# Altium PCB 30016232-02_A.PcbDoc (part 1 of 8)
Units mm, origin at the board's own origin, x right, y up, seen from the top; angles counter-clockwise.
Board outline 210 x 130 mm, 8 copper layers (1-TOP, 2-GND, 3-INTOP, 4-PWR, 5-PWR, 6-INBOT, 7-GND, 8-BOTTOM), stack 1.646 mm thick; 754 components, 649 nets, 2976 pads, 2161 vias.
Unrouted connection lines stored in the file: 22.
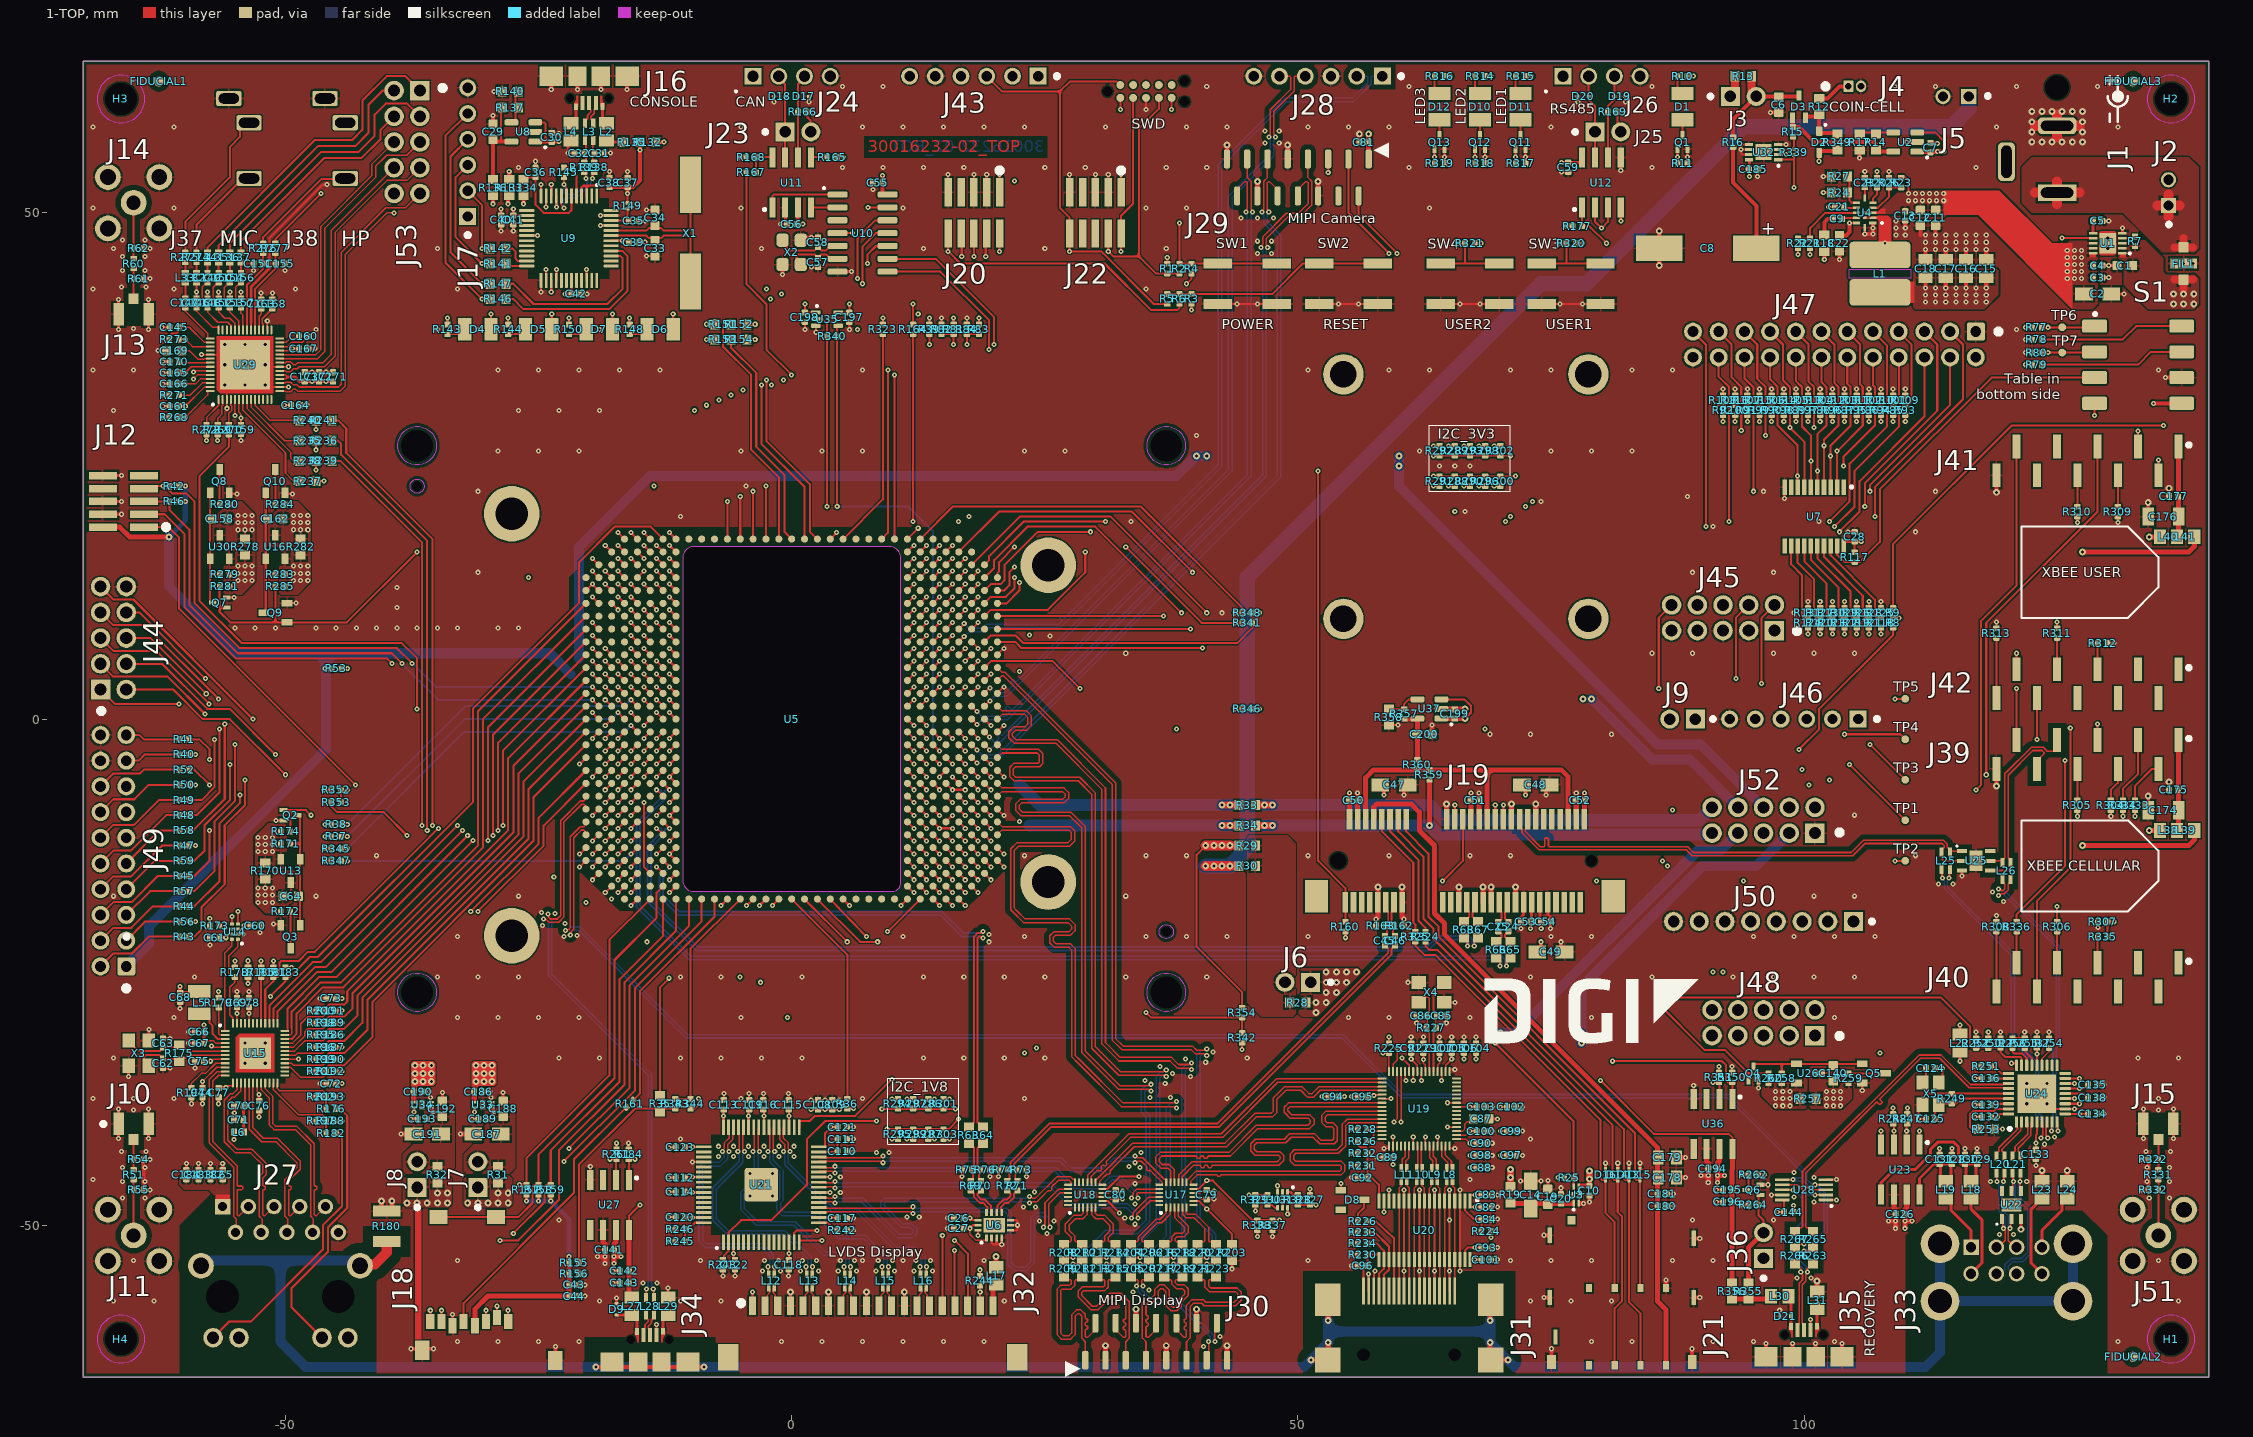
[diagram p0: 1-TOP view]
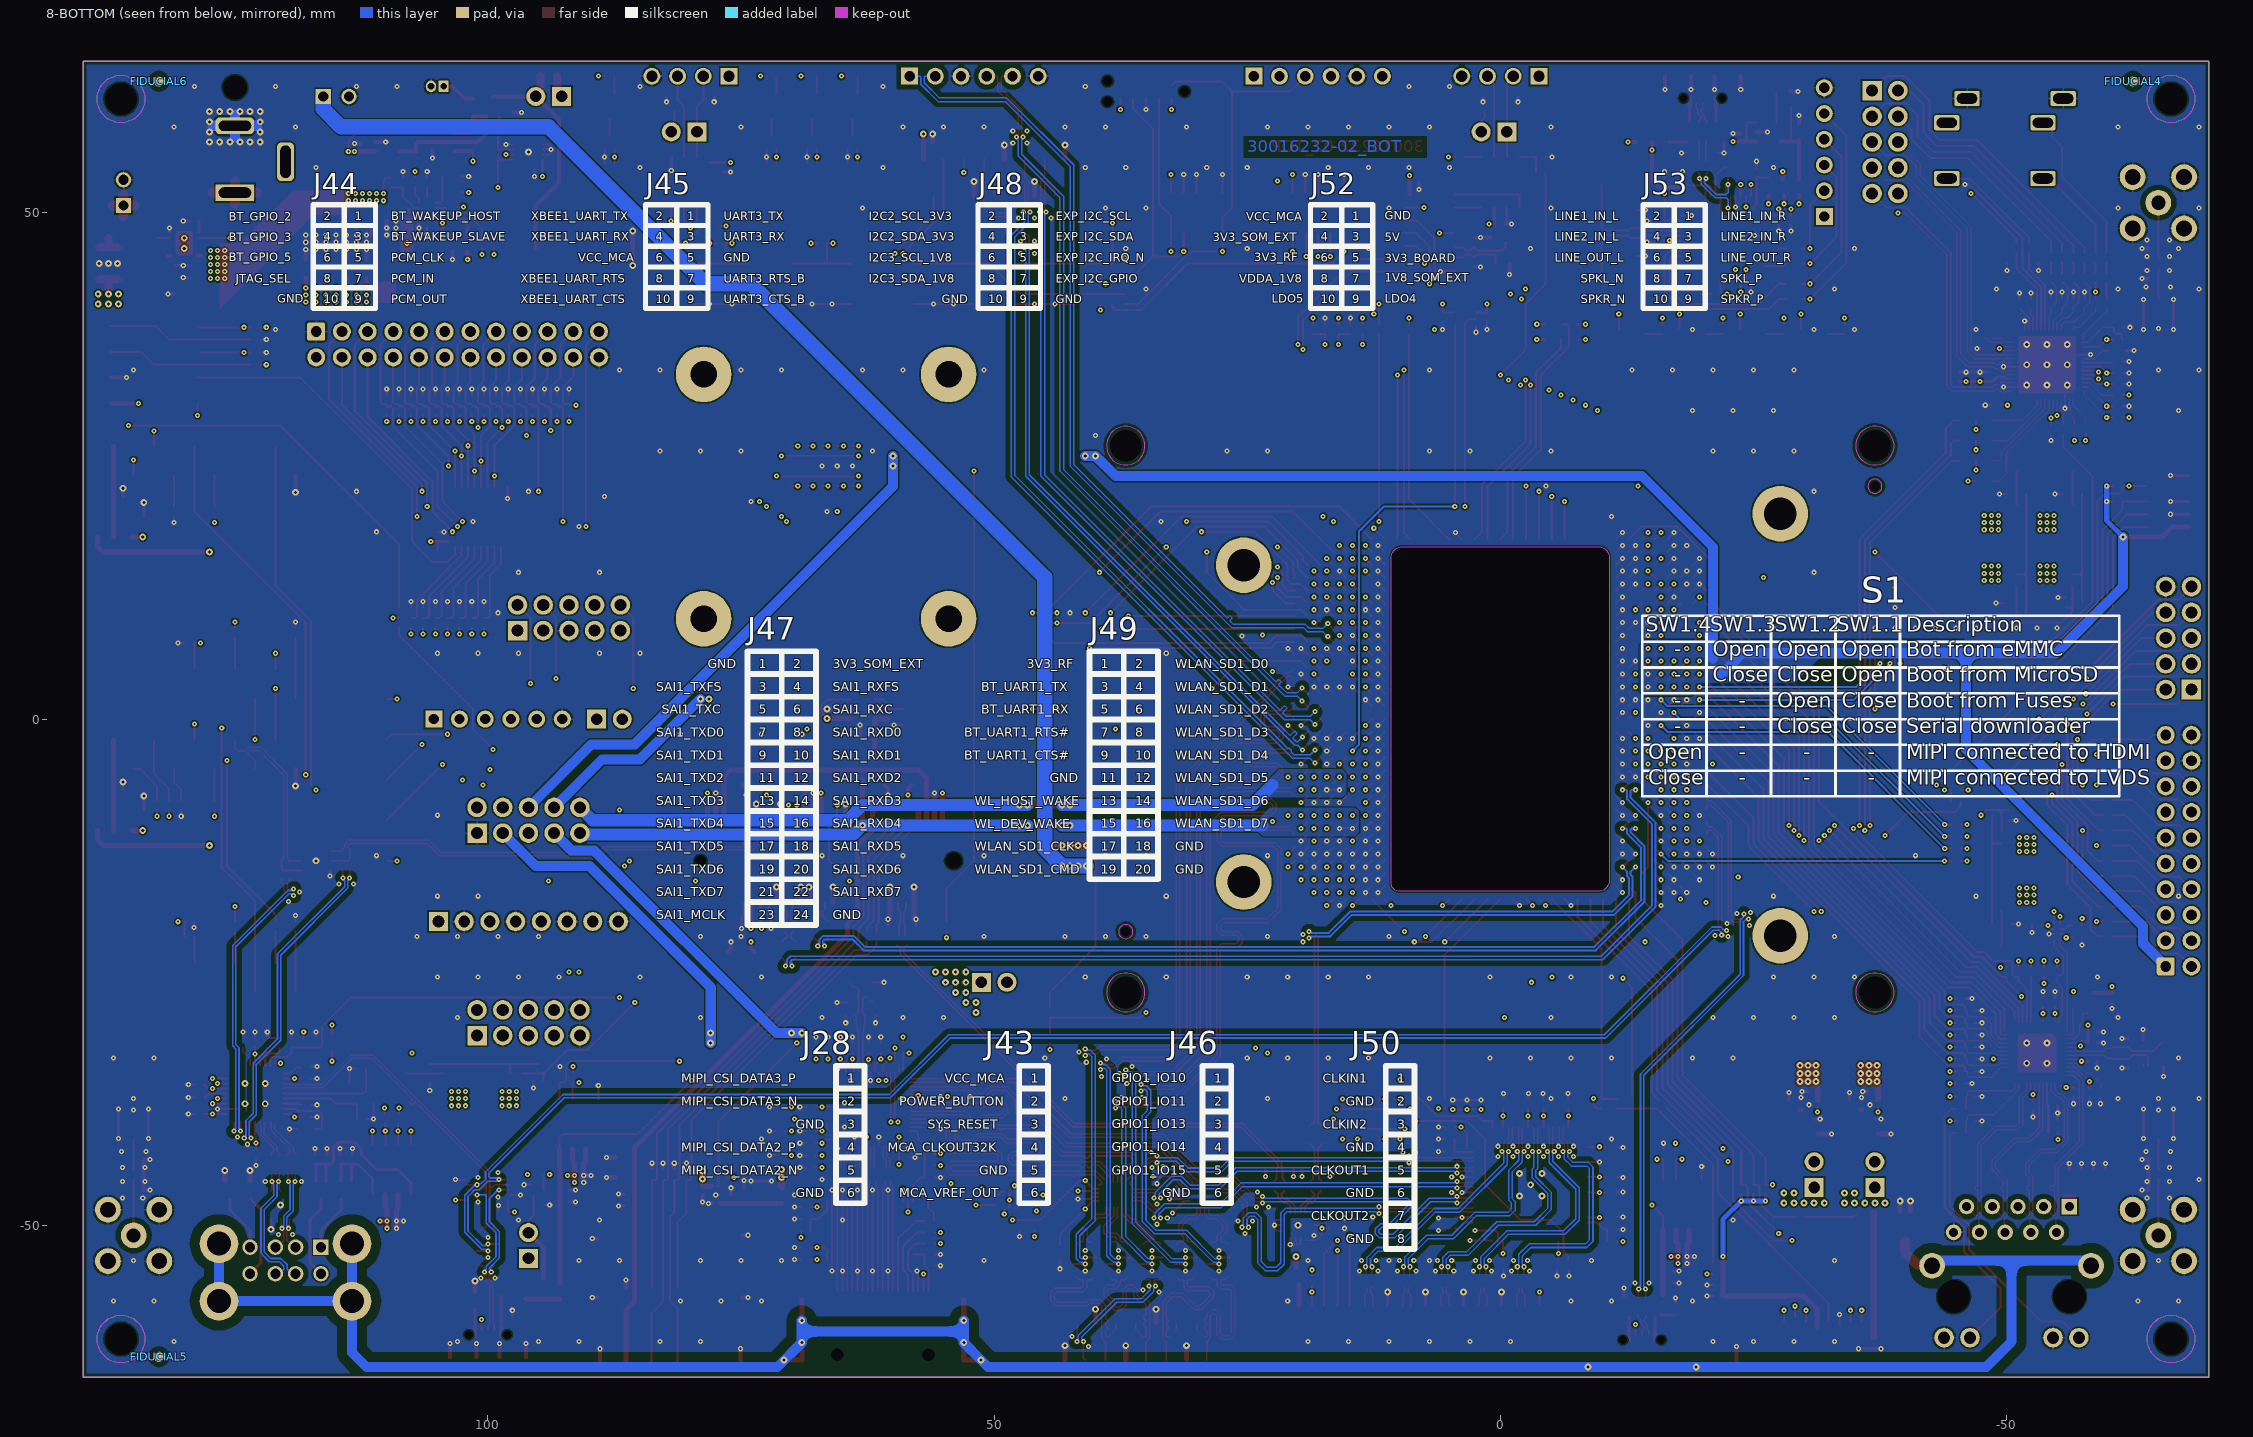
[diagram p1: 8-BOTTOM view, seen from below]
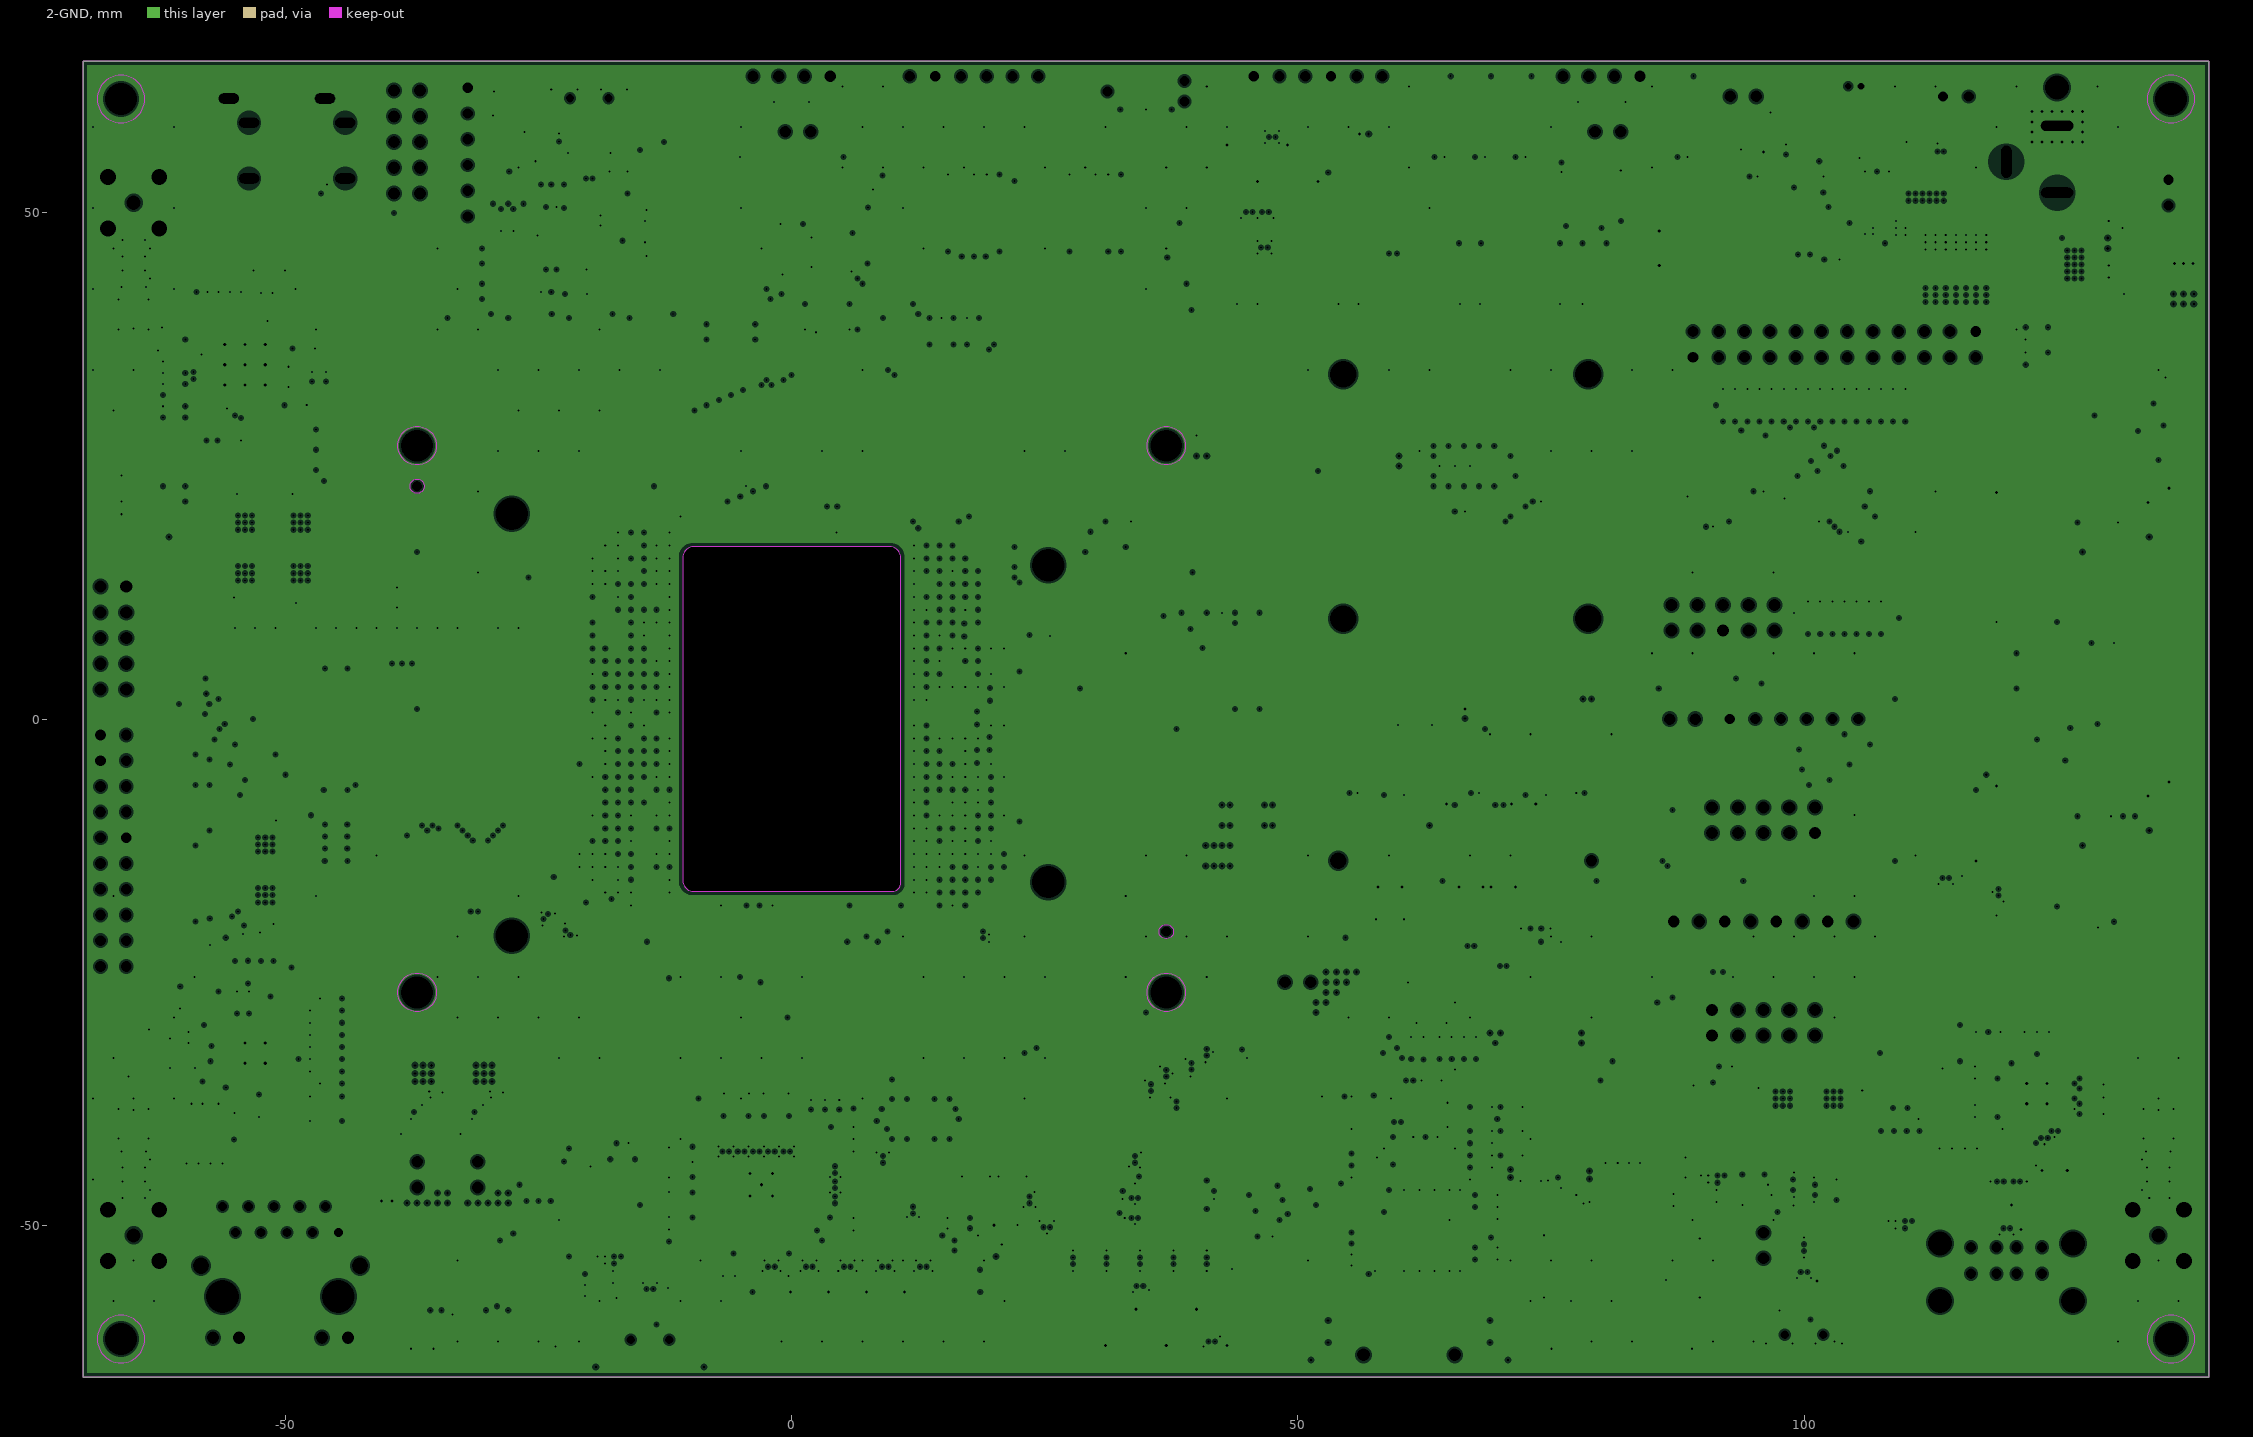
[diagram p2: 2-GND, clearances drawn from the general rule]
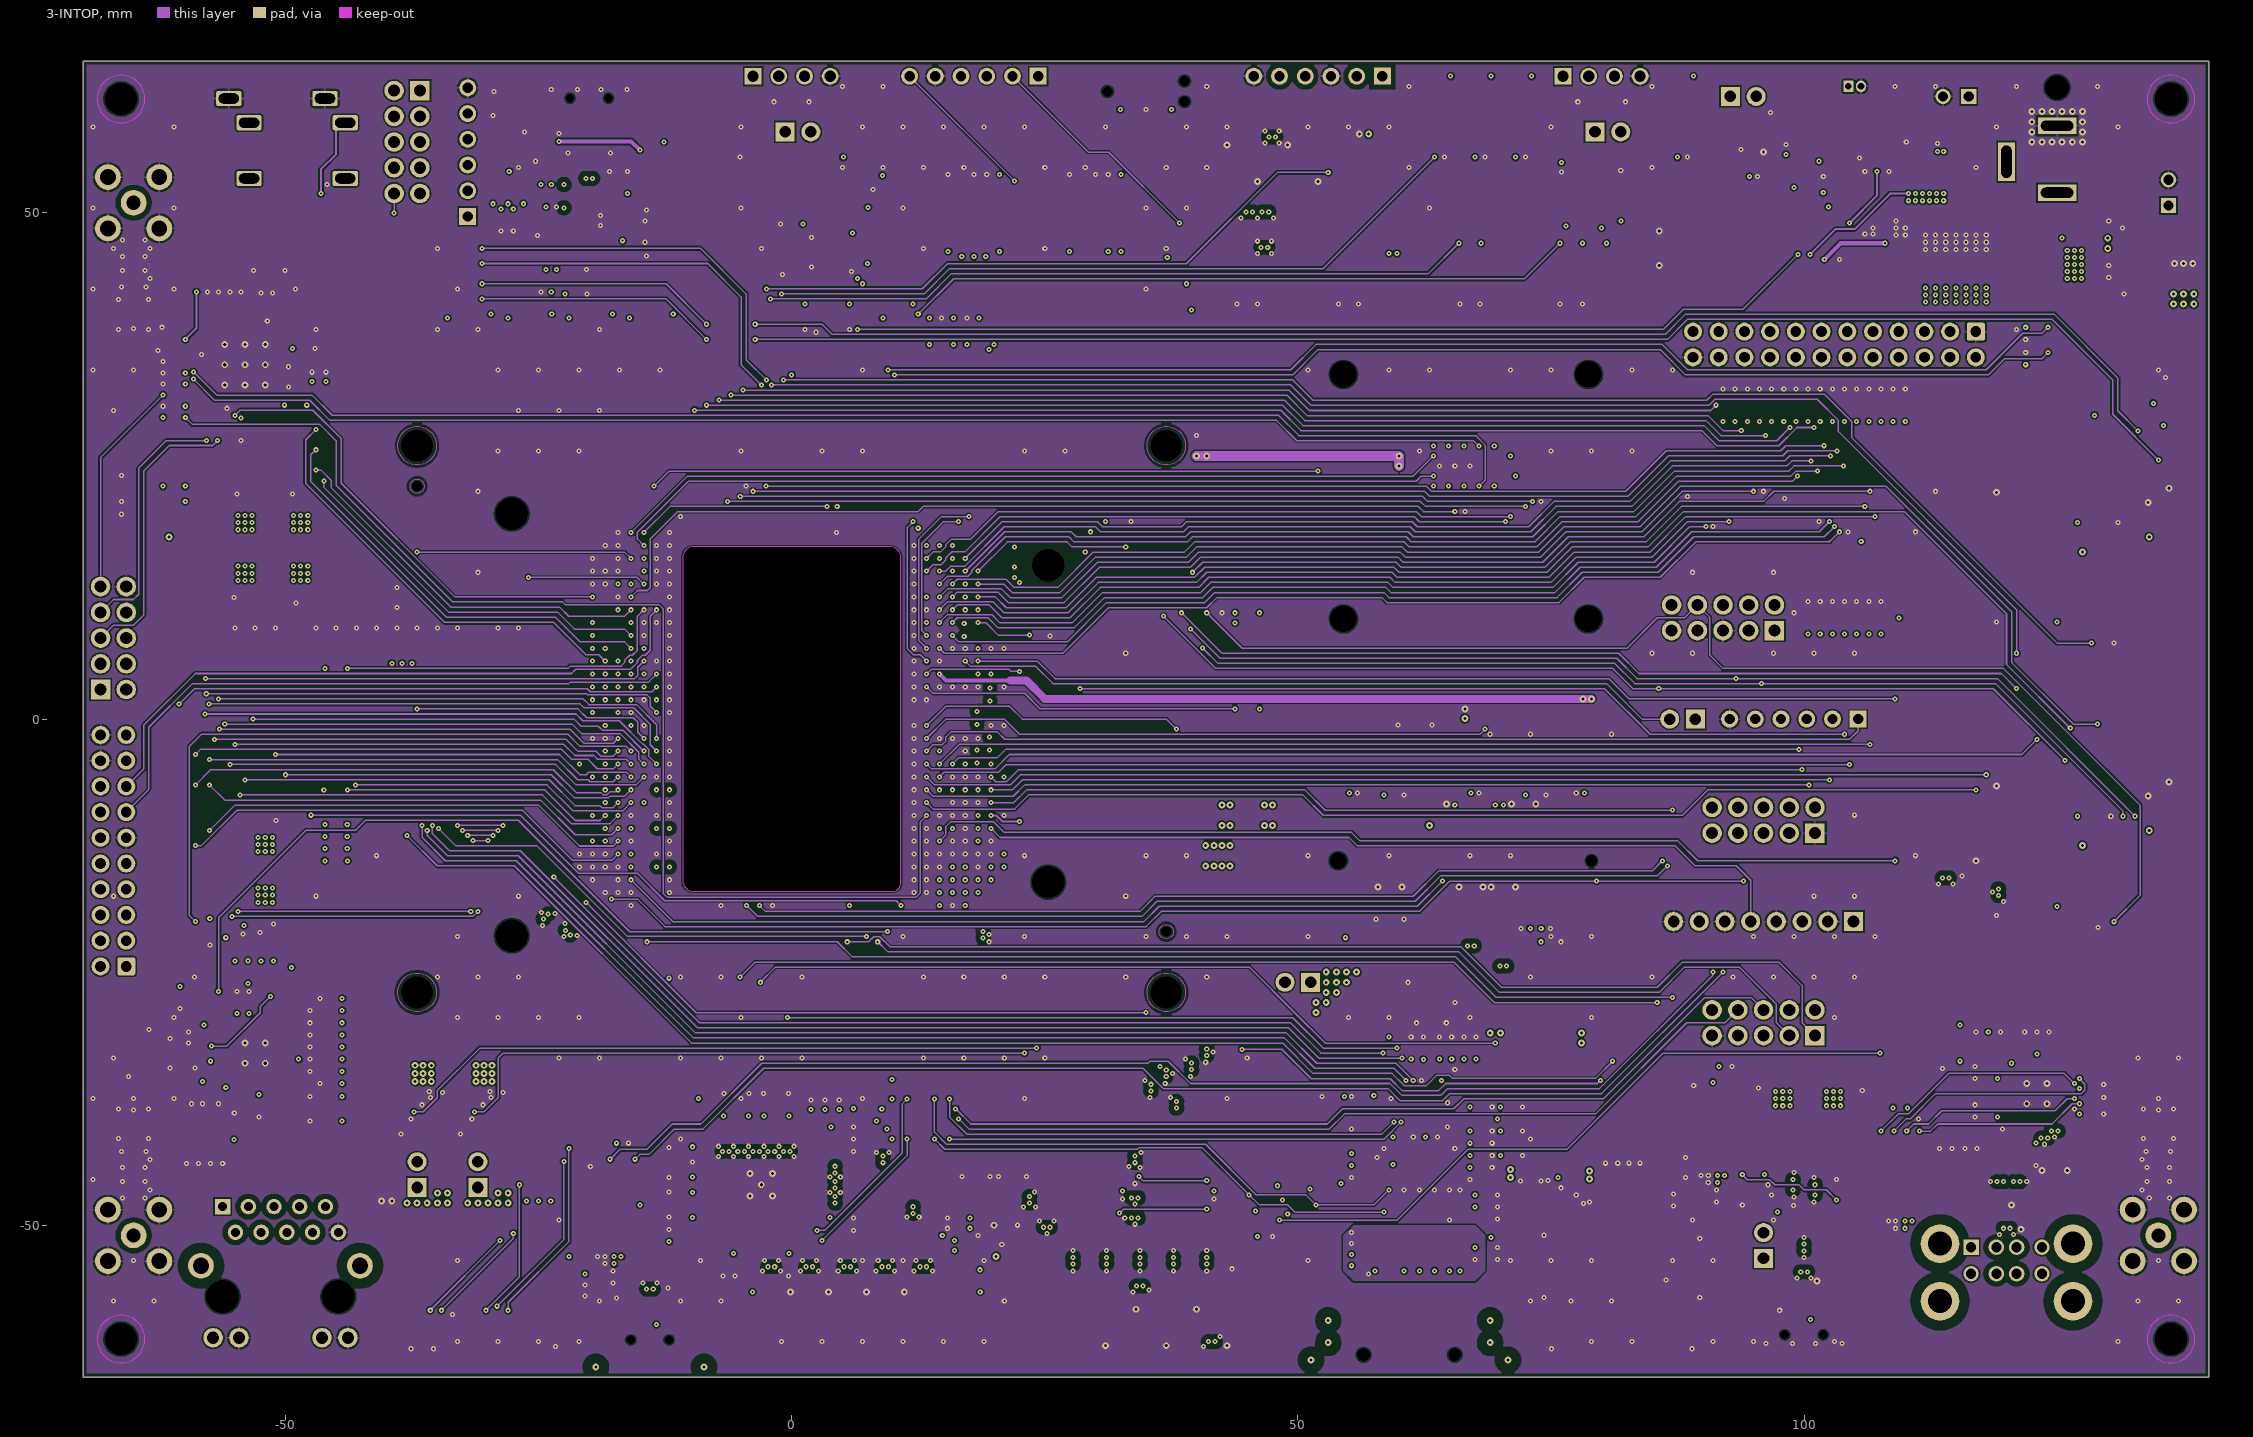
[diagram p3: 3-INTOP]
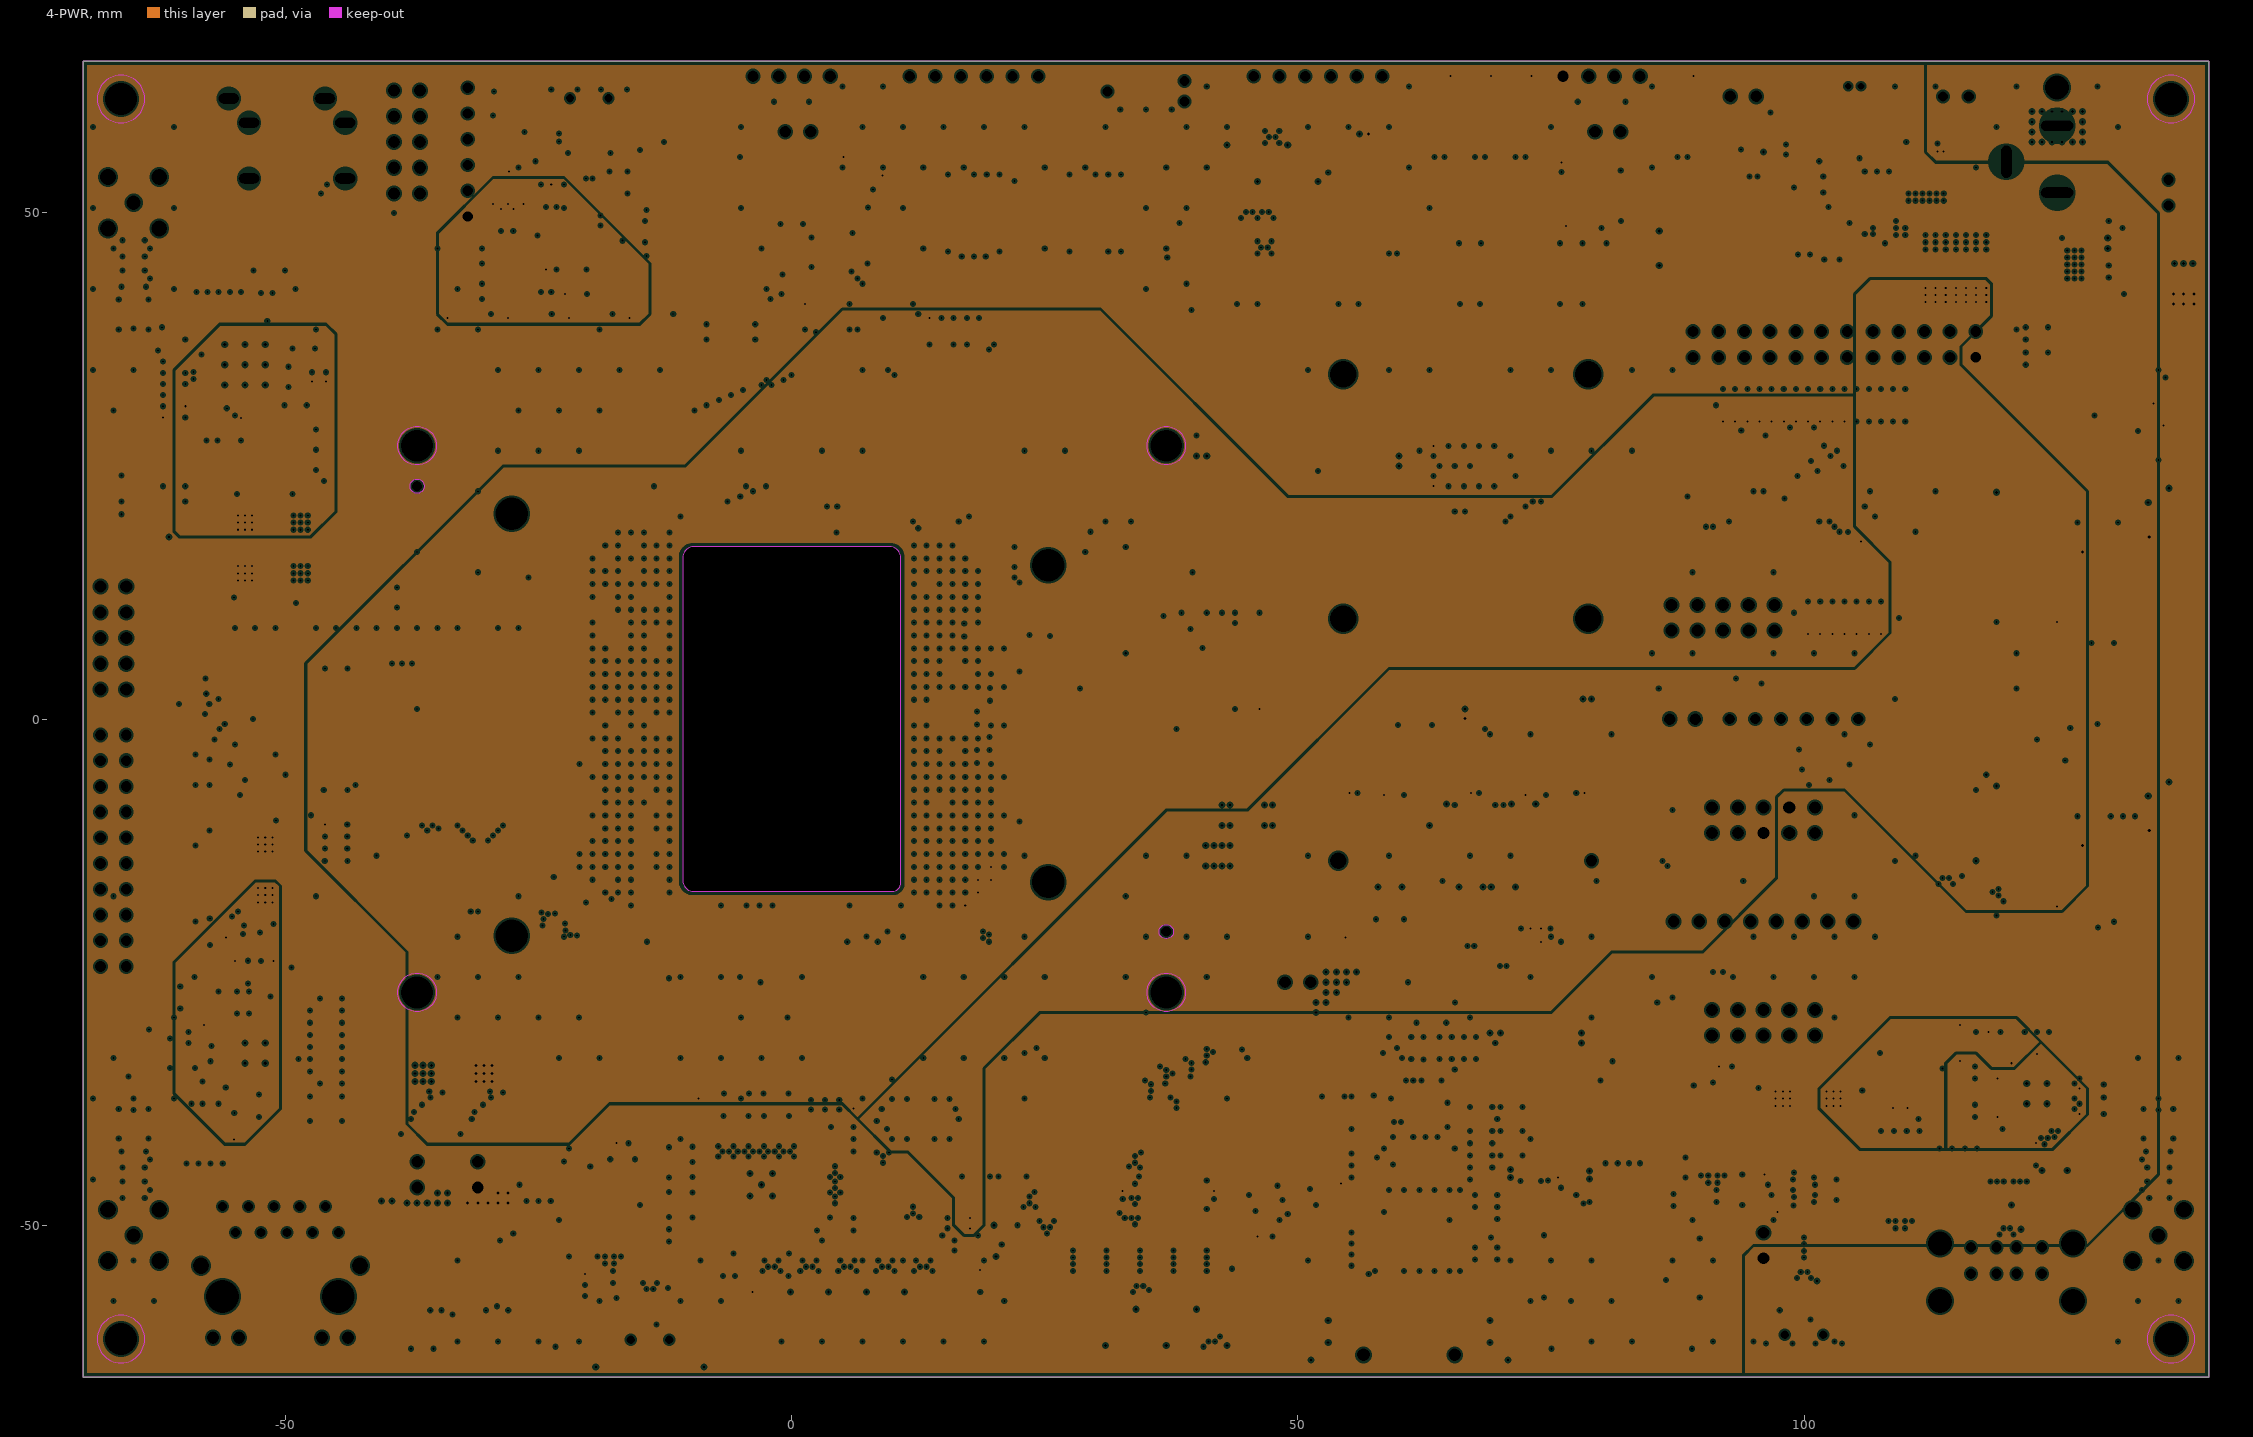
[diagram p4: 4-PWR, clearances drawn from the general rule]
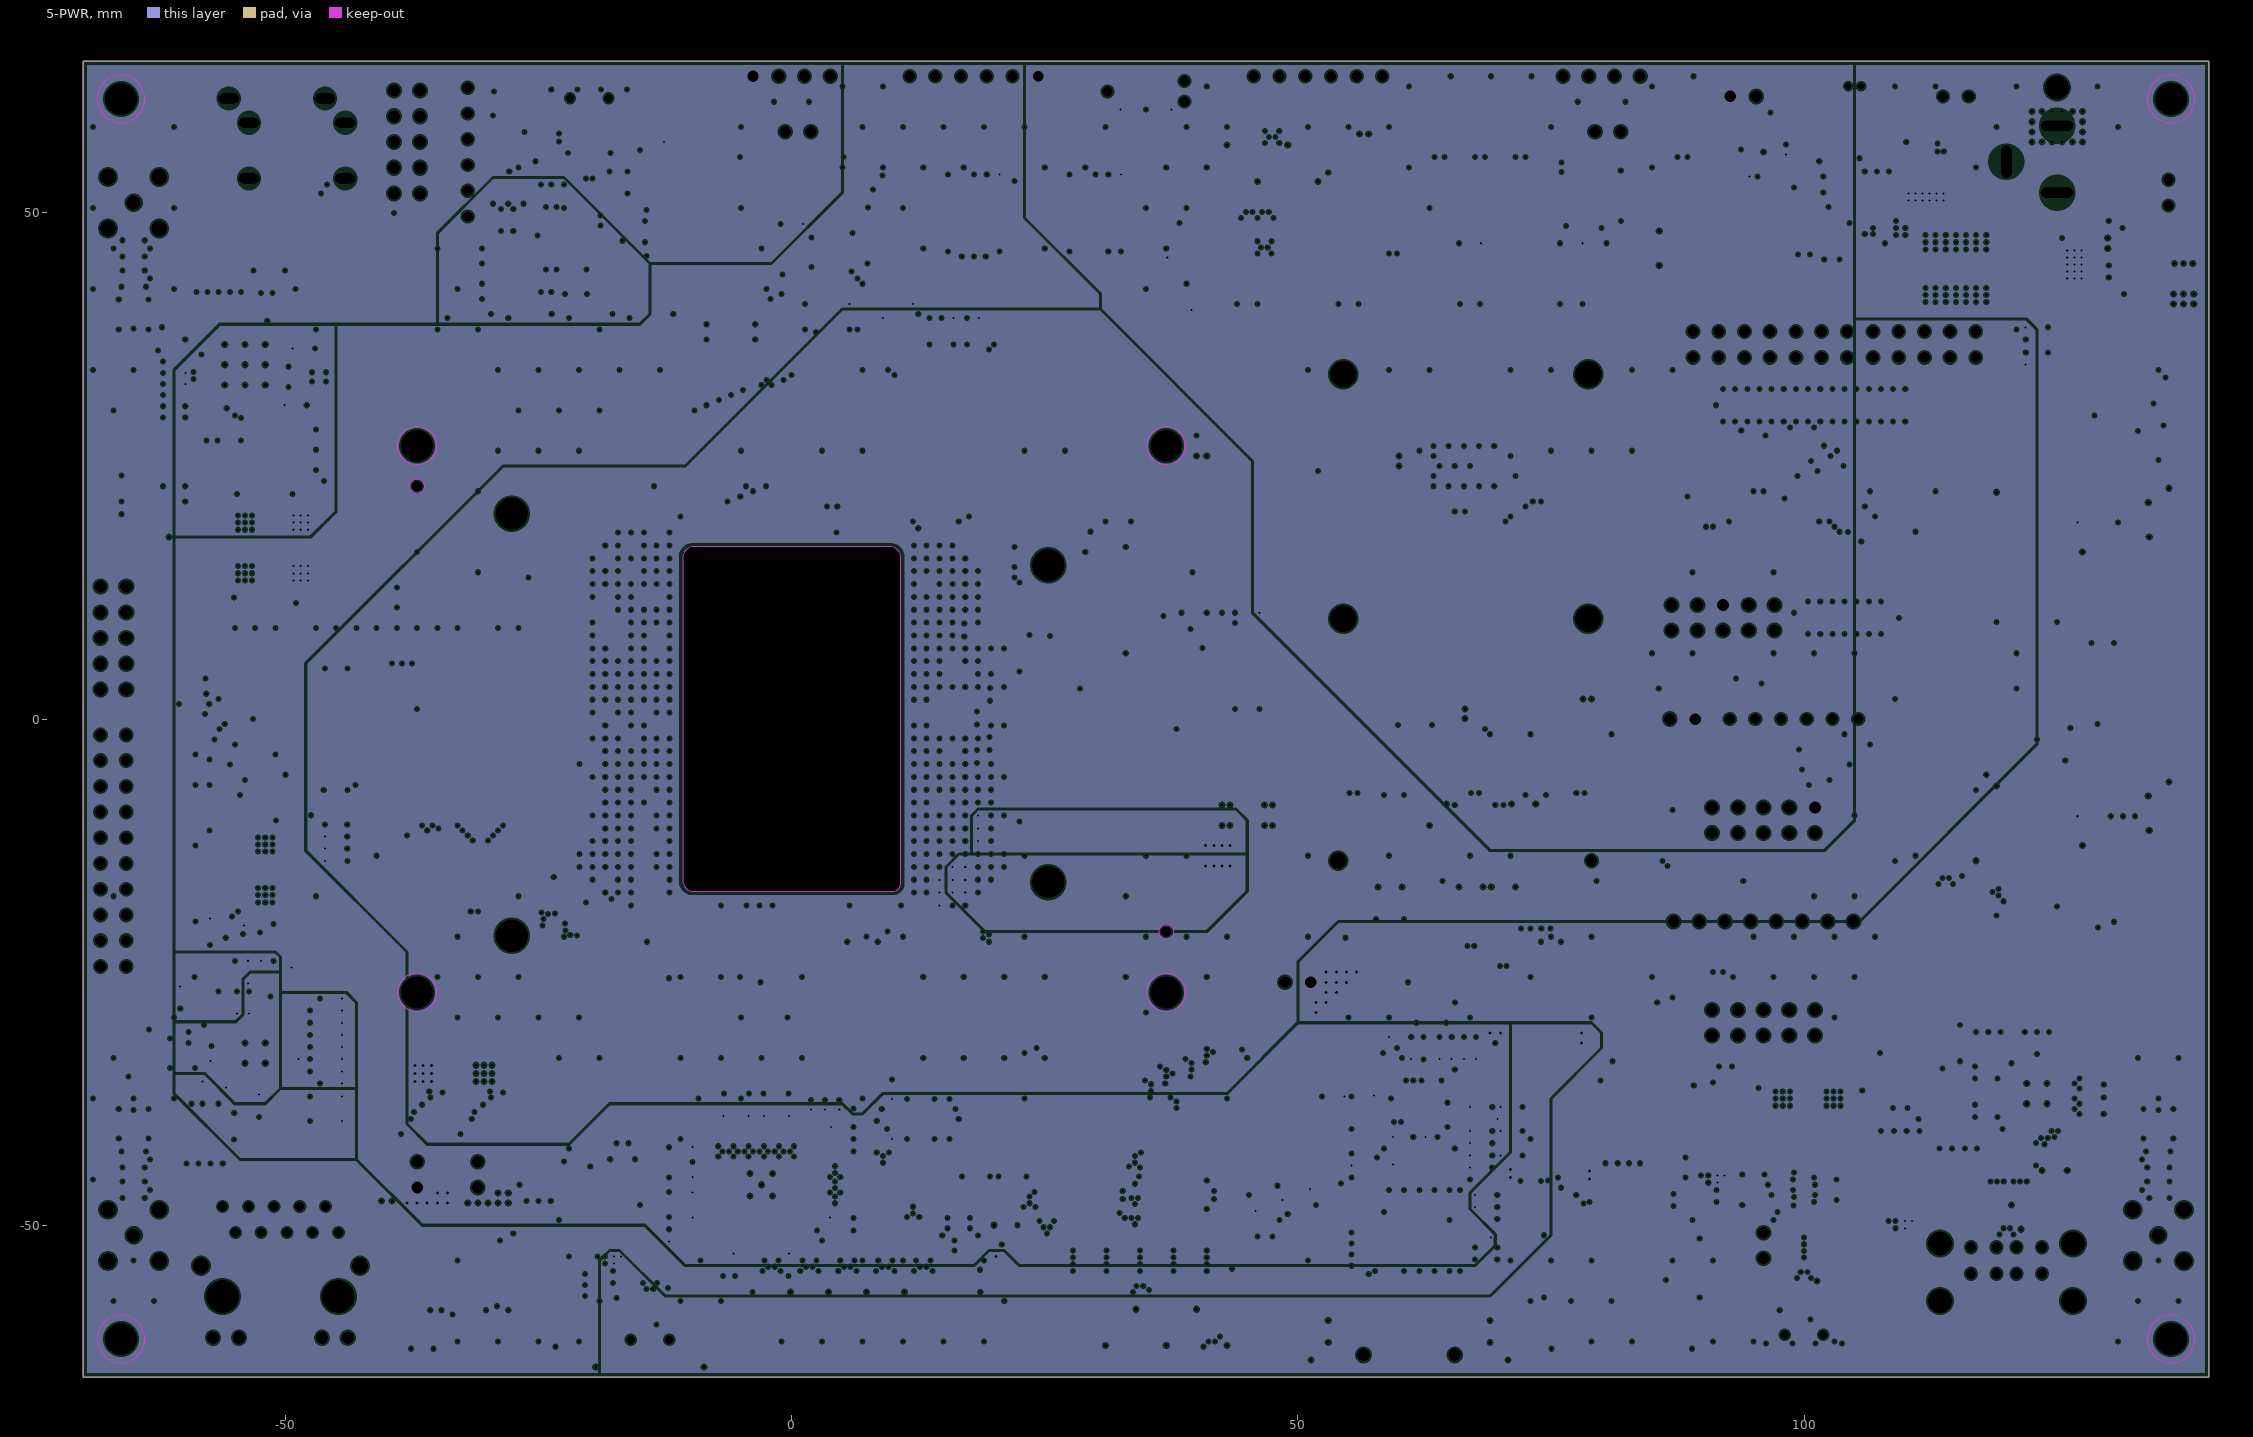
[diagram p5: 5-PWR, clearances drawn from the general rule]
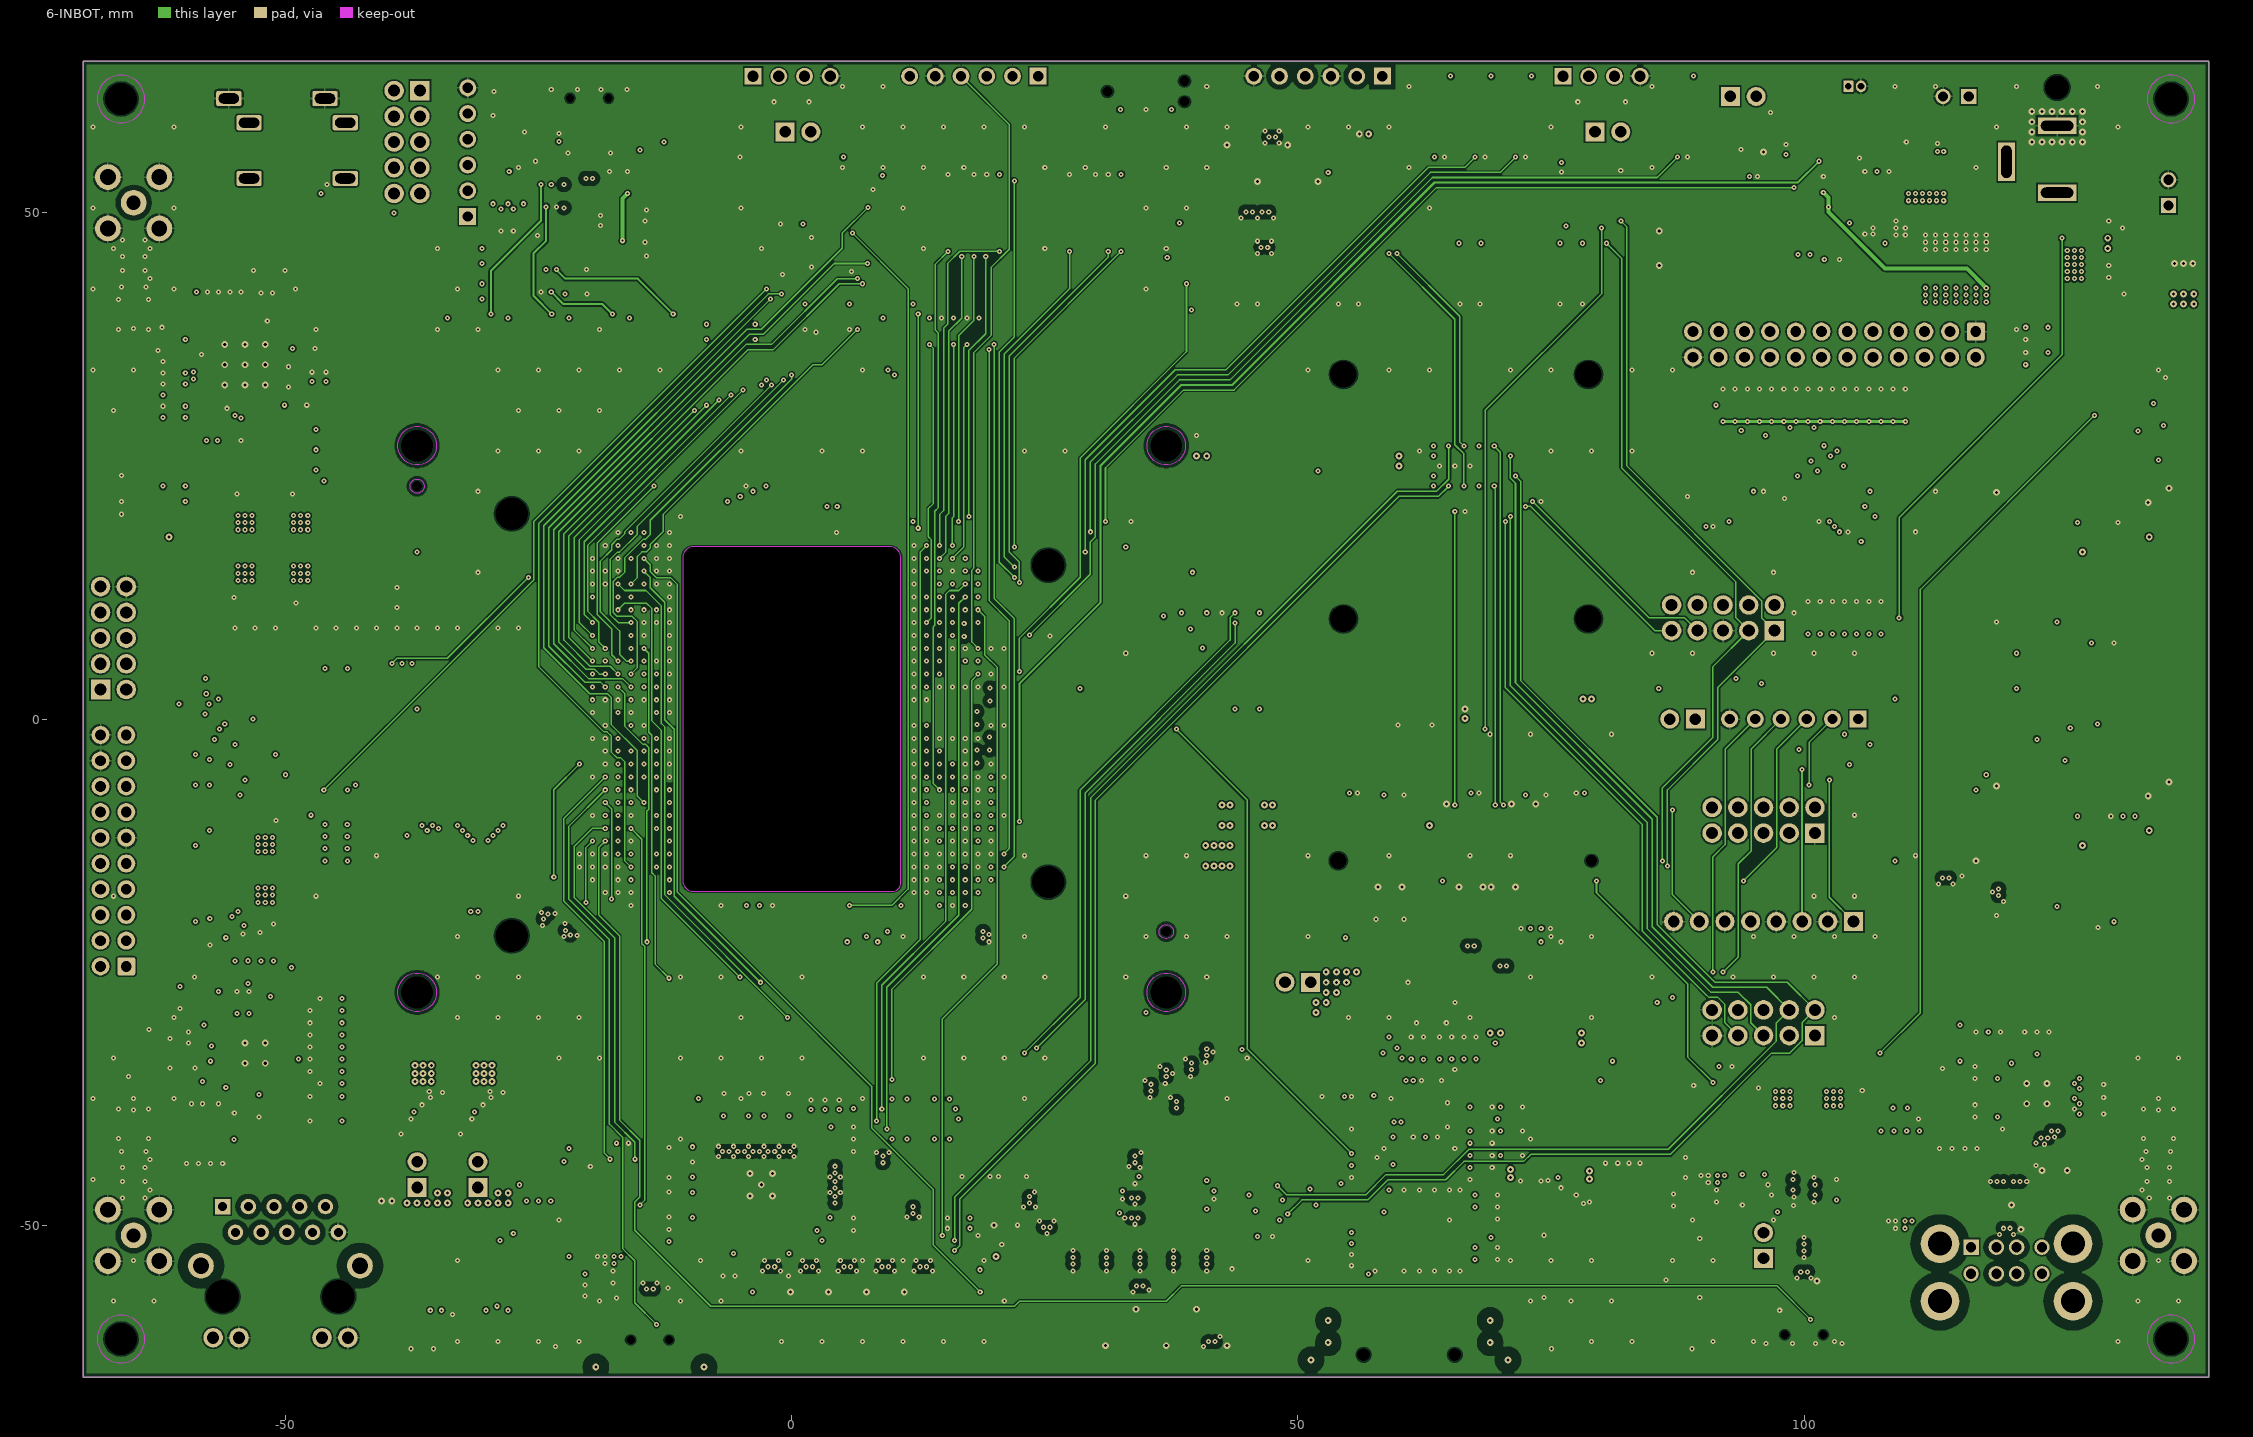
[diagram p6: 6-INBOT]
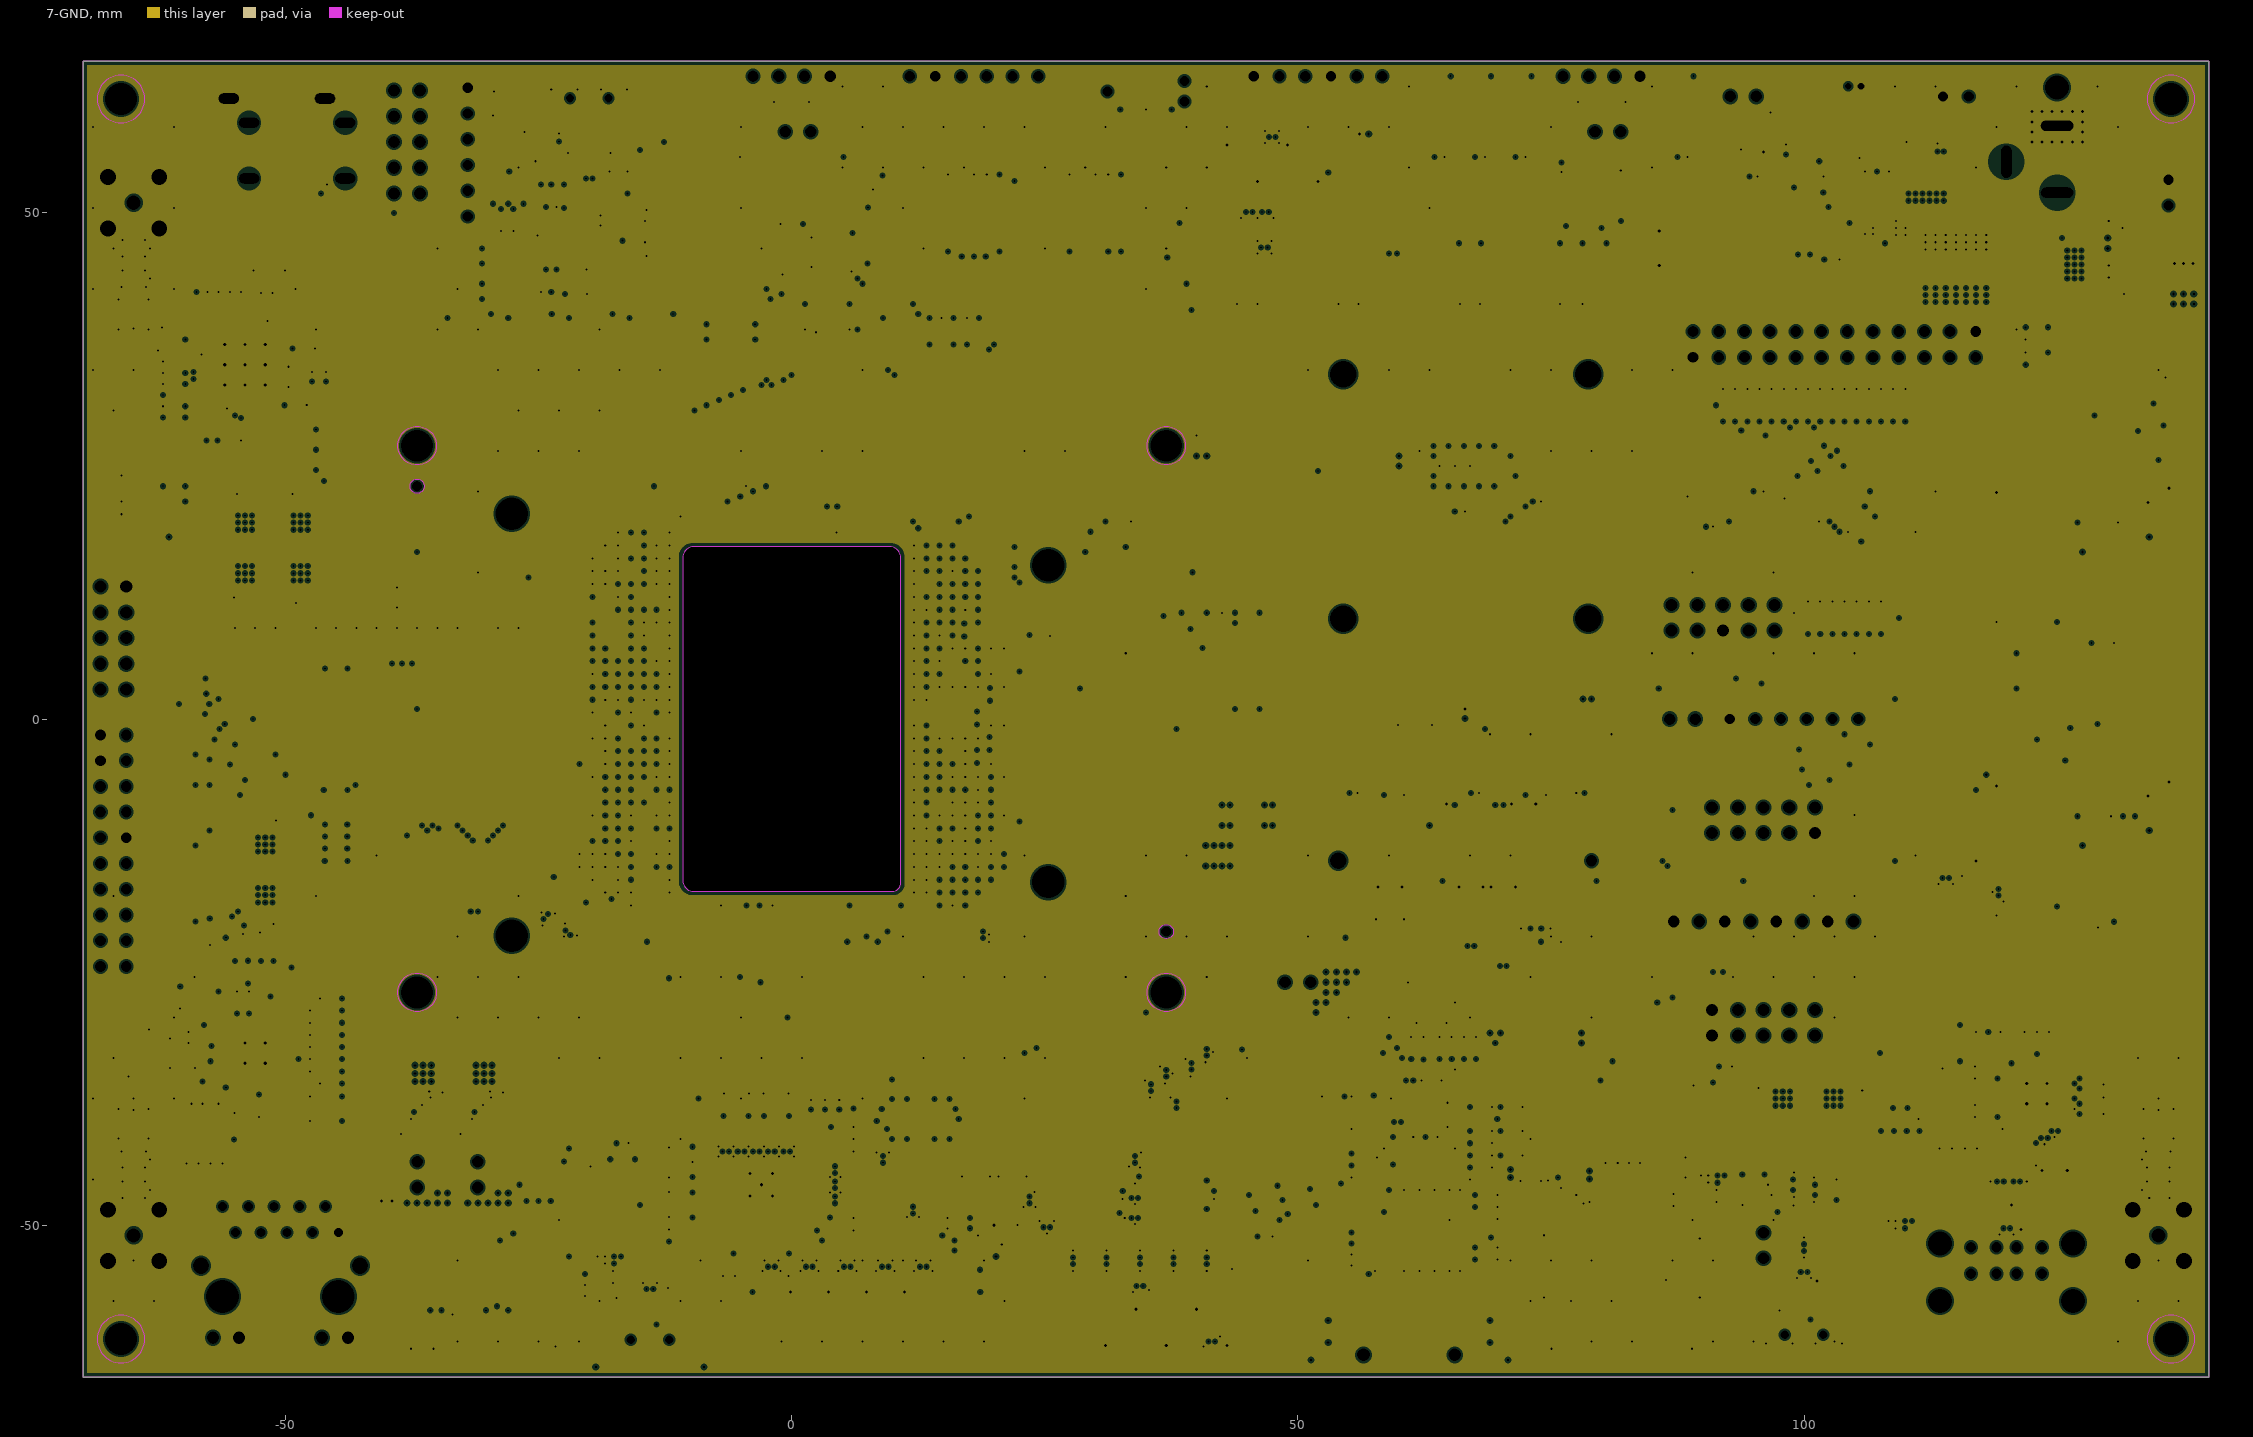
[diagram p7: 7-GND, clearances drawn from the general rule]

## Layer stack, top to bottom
Top Solder: solder mask 0.01, SM-001, Dk 4
1-TOP: signal copper 0.018
Dielectric1: prepreg 0.12, PP-017, Dk 4.2
2-GND: plane copper 0.035, net GND
Dielectric2: core 0.3, Core-015, Dk 4.2
3-INTOP: signal copper 0.035
Dielectric3: prepreg 0.18, PP-017, Dk 4.2
4-PWR: plane copper 0.035, net (Multiple Nets)
Dielectric6: core 0.2, Core-036, Dk 4.2
5-PWR: plane copper 0.035, net (Multiple Nets)
Dielectric10: prepreg 0.18, PP-017, Dk 4.2
6-INBOT: signal copper 0.035
Dielectric 12: core 0.3, Core-015, Dk 4.2
7-GND: plane copper 0.035, net GND
Dielectric11: prepreg 0.12, PP-017, Dk 4.2
8-BOTTOM: signal copper 0.018
Bottom Solder: solder mask 0.01, SM-001, Dk 4

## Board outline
-70,-65 -70,65 140,65 140,-65

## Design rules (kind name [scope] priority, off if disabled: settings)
Clearance Clearance_EDGE [OnLayer('Keep-Out Layer')] p1: gap=0.3 ignorepadtopadclearanceinfootprint=FALSE
Clearance Clearance_SHLD [InNet('SHLD')] p2: gap=1 ignorepadtopadclearanceinfootprint=FALSE
Clearance Clearance_Pair&Ant [InNetClass('DIFF85') or InNetClass('DIFF90') or InNetClass('DIFF100') or InNetClass('ANT') vs InNamedPolygon('GND_PLANE')] p3: gap=0.5 ignorepadtopadclearanceinfootprint=FALSE
Clearance Clearance_Planes [All vs InNamedPolygon('GND_PLANE')] p4: gap=0.15 ignorepadtopadclearanceinfootprint=FALSE
Clearance [All] p5: gap=0.15 ignorepadtopadclearanceinfootprint=FALSE
ComponentClearance [All] p1: gap=0.2 collisioncheckmode=3 verticalgap=0.2 showdistances=FALSE
DiffPairsRouting DiffPairsRouting_100R [InNetClass('DIFF100')] p1: maxlimit=0.204 minlimit=0.204 mostfreqgap=0.204 toplayer_minwidth=0.15 toplayer_maxwidth=0.15 toplayer_prefwidth=0.15 midlayer1_minwidth=0.15 midlayer1_maxwidth=0.15 midlayer1_prefwidth=0.15 midlayer2_minwidth=0.15 midlayer2_maxwidth=0.15 midlayer2_prefwidth=0.15 bottomlayer_minwidth=0.15 bottomlayer_maxwidth=0.15 bottomlayer_prefwidth=0.15 maxuncoupledlength=12.7
DiffPairsRouting DiffPairsRouting_85R [InNetClass('DIFF85')] p2: maxlimit=0.15 minlimit=0.15 mostfreqgap=0.15 toplayer_minwidth=0.192 toplayer_maxwidth=0.192 toplayer_prefwidth=0.192 midlayer1_minwidth=0.192 midlayer1_maxwidth=0.192 midlayer1_prefwidth=0.192 midlayer2_minwidth=0.192 midlayer2_maxwidth=0.192 midlayer2_prefwidth=0.192 bottomlayer_minwidth=0.192 bottomlayer_maxwidth=0.192 bottomlayer_prefwidth=0.192 maxuncoupledlength=12.7
DiffPairsRouting DiffPairsRouting_90R [InNetClass('DIFF90')] p3: maxlimit=0.15 minlimit=0.15 mostfreqgap=0.15 toplayer_minwidth=0.168 toplayer_maxwidth=0.168 toplayer_prefwidth=0.168 midlayer1_minwidth=0.168 midlayer1_maxwidth=0.168 midlayer1_prefwidth=0.168 midlayer2_minwidth=0.168 midlayer2_maxwidth=0.168 midlayer2_prefwidth=0.168 bottomlayer_minwidth=0.168 bottomlayer_maxwidth=0.168 bottomlayer_prefwidth=0.168 maxuncoupledlength=12.7
Height [All] p1: minheight=0 maxheight=100 prefheight=20
HoleSize [All] p1: absolutevalues=TRUE maxlimit=10 minlimit=0.1 maxpercent=80.000 minpercent=20.000
MatchedLengths [All] p1: tolerance=0.1 checknetsindiffpair=TRUE checkdiffpairvsdiffpair=FALSE checkxsignals=FALSE checkothers=FALSE
MinimumSolderMaskSliver [All] p1: minsoldermaskwidth=0.1
PlaneClearance PlaneClearance_SHLD [InNet('SHLD')] p1: clearance=1
PlaneClearance PlaneClearance_ANT [InNetClass('ANT')] p2: clearance=0.5
PlaneClearance [All] p3: clearance=0.2
PlaneConnect PlaneConnect_VIA [IsVia] p1: planeconnectstyle=Direct reliefexpansion=0.15 reliefentries=4 reliefconductorwidth=0.2 reliefairgap=0.2
PlaneConnect [All] p2: planeconnectstyle=Relief reliefexpansion=0.15 reliefentries=4 reliefconductorwidth=0.2 reliefairgap=0.2
PolygonConnect PolygonConnect_VIA [IsVia] p1: connectstyle=Direct reliefconductorwidth=0.2 reliefentries=4 polygonreliefangle="90 Angle" airgapwidth=0.2
PolygonConnect [All] p2: connectstyle=Relief reliefconductorwidth=0.2 reliefentries=4 polygonreliefangle="90 Angle" airgapwidth=0.2
RoutingVias [All] p1: holewidth=0.3 width=0.68 viastyle="Through Hole" minholewidth=0.2 minwidth=0.5 maxholewidth=1 maxwidth=1
SolderMaskExpansion [All] p1: expansion=0.102
Width [All] p1: maxlimit=14 minlimit=0.15 preferedwidth=0.2
23 further rules are at their usual default settings.

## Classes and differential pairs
component class "05 - CCIMX8M Nano Digital interfaces": C197 C198 R340 R352 R353 U35
net class ANT: NetJ10_1 NetJ11_1 NetJ13_1 NetJ14_1 NetJ15_1 NetJ51_1
component class "09 - JTAG, SWD, uSD, Mini PCIe, uSIM": C43 C44 C45 C46 C47 C48 C49 C50 C51 C52 C53 C54 C178 C179 C180 C181 C199 C200 D13 D14 D15 D16 J15 J18 J19 J20 J21 J22 J51 R155 R156 R157 R158 R159 R160 R161 R162 R163 R164 R322 R324 R325 R331 R332 R357 R358 R359 R360 SWD U37
component class "16 - USB Recovery, USB OTG": C141 C142 C143 C144 C194 C195 C196 D9 D21 J34 J35 J36 L27 L28 L29 L30 L31 Q6 R184 R261 R262 R263 R264 R265 R266 R267 R342 R350 R351 R354 R355 R356 U27 U28 U36
component class "07 - Bootstrap": C28 R77 R78 R79 R80 R81 R82 R83 R84 R85 R86 R87 R88 R89 R90 R91 R92 R93 R94 R95 R96 R97 R98 R99 R100 R101 R102 R103 R104 R105 R106 R107 R108 R109 R110 R111 R112 R113 R114 R115 R116 R117 R118 R119 R120 R121 R122 R123 R124 R125 R126 R127 R128 R129 R130 R131 S1 TP6 TP7 U7
net class 0.2A: 3V3_DBG NetD3_1 NetD4_2 NetD4_3 VCC_MCA VCC_RTC
component class "13 - MIPI to HDMI bridge": C82 C83 C84 C85 C86 C87 C88 C89 C90 C91 C92 C93 C94 C95 C96 C97 C98 C99 C100 C101 C102 C103 C104 C105 C106 C107 D8 J31 L8 L9 L10 L11 R224 R225 R226 R227 R228 R229 R230 R231 R232 R233 R234 R235 R236 R237 R238 R239 R240 R241 R326 R327 R328 R329 R330 U19 U20 U31 X4
component class "10 - RS485, CAN": C55 C56 C57 C58 C59 D17 D18 D19 D20 J23 J24 J25 J26 R165 R166 R167 R168 R169 R177 U10 U11 U12 X2
component class "08 - Consoles": C29 C30 C31 C32 C33 C34 C35 C36 C37 C38 C39 C40 C41 C42 D4 D5 D6 D7 J16 J17 L2 L3 L4 R132 R133 R134 R135 R136 R137 R138 R139 R140 R141 R142 R143 R144 R145 R146 R147 R148 R149 R150 R151 R152 R153 R154 U8 U9 X1
net class miniPCIe: PCIE_CLK_N PCIE_CLK_P PCIE_DIS_N PCIE_I2C_SCL PCIE_I2C_SDA PCIE_RESET_N PCIE_RX_N PCIE_RX_P PCIE_TX_N PCIE_TX_P PCIE_WAKE_N PCIECLK_N PCIECLK_P USB_PCIe_D_N USB_PCIe_D_P
net class "micro SD": NetJ16_5 USDHC2_CD_B USDHC2_CLK USDHC2_CMD USDHC2_DATA0 USDHC2_DATA1 USDHC2_DATA2 USDHC2_DATA3
net class PCM: PCM_CLK PCM_IN PCM_OUT PCM_SYNC
net class RGMII2: RGMII_MDC_3V3 RGMII_MDIO_3V3
net class RGMII1: "RGMII_INT_ B" RGMII_MDC RGMII_MDC_3V3 RGMII_MDIO RGMII_MDIO_3V3 RGMII_TD0 RGMII_TD1 RGMII_TD2 RGMII_TD3 RGMII_TX_CTL RGMII_TXC
net class MIPI_CSIO: MIPI_CSI_CLK_N MIPI_CSI_CLK_P MIPI_CSI_DATA0_N MIPI_CSI_DATA0_P MIPI_CSI_DATA1_N MIPI_CSI_DATA1_P MIPI_CSI_RESET_N
net class MIPI_DSI0: LVDS_IRQ_N MIPI_DSI_CLK_N MIPI_DSI_CLK_P MIPI_DSI_DATA0_N MIPI_DSI_DATA0_P MIPI_DSI_DATA1_N MIPI_DSI_DATA1_P MIPI_DSI_DATA2_N MIPI_DSI_DATA2_P MIPI_DSI_DATA3_N MIPI_DSI_DATA3_P
net class 5A: NetFIL1_1 VIN VIN_PROT
net class "micro SIM": PCIE_UIM_CLK PCIE_UIM_DATA PCIE_UIM_PWR PCIE_UIM_RST PCIE_UIM_VPP
component class "21 - History, Mechanicals": FIDUCIAL1 FIDUCIAL2 FIDUCIAL3 FIDUCIAL4 FIDUCIAL5 FIDUCIAL6 H1 H2 H3 H4
net class Power: 1V8 1V8_CODEC 1V8_SOM_EXT 3V3 3V3_BOARD 3V3_CODEC 3V3_ETH 3V3_RF 3V3_SOM_EXT 3V3_USB 5V DVDDL1 GND NetC14_1 NetC43_2 NetC75_2 NetC128_2 NetC132_2 NetC147_2 NetC155_1 NetD3_1 NetD6_A NetFIL1_1 NetJ6_2 NetJ33_A1 NetJ33_A4 NetJ33_B1 NetJ33_B4 NetJ40_7 NetL5_1 NetQ8_D NetR14_1 NetR165_1 NetR185_2 SHLD VCC_LICELL VCC_MCA VDDH1 VDDIO1 VIN VIN_PROT XBEE1_VCC
component class "12 - MIPI display and switch, MIPI camera": C79 C80 C81 J29 J30 R203 R204 R205 R206 R207 R208 R209 R210 R211 R212 R213 R214 R215 R216 R217 R218 R219 R220 R221 R222 R223 R337 R338 U17 U18
component class "04 - CCIMX8M Nano Power, Control, MCA": C186 C187 C188 C189 C190 C191 C192 C193 J6 J7 J8 J9 R28 R29 R30 R31 R32 R33 R34 R35 R36 R37 R38 R39 R323 R341 R343 R344 R345 R346 R347 R348 TP1 TP2 TP3 TP4 TP5 U5 U33 U34
component class "03 - Power, reset": C1 C2 C3 C4 C5 C6 C7 C8 C9 C10 C11 C12 C13 C14 C15 C16 C17 C18 C19 C20 C21 C22 C23 C185 D1 D2 D3 FIL1 J1 J2 J3 J4 J5 L1 Q1 R1 R2 R3 R4 R5 R6 R7 R8 R9 R10 R11 R12 R13 R14 R15 R16 R17 R18 R19 R20 R21 R22 R23 R24 R25 R26 R27 R339 R349 SW1 SW2 U1 U2 U3 U4 U32
component class "14 - MIPI to LVDS bridge": C108 C109 C110 C111 C112 C113 C114 C115 C116 C117 C118 C119 C120 C121 C122 C123 J32 L12 L13 L14 L15 L16 L17 R242 R243 R244 R245 R246 U21
component class "11 - Ethernet": C60 C61 C62 C63 C64 C65 C66 C67 C68 C69 C70 C71 C72 C73 C74 C75 C76 C77 C78 C182 C183 C184 J27 L5 L6 L7 Q2 Q3 R170 R171 R172 R173 R174 R175 R176 R178 R179 R180 R181 R182 R183 R185 R186 R187 R188 R189 R190 R191 R192 R193 R194 R195 R196 R197 R198 R199 R200 R201 R202 U13 U14 U15 X3
component class "15 - USB HUB": C124 C125 C126 C127 C128 C129 C130 C131 C132 C133 C134 C135 C136 C137 C138 C139 C140 J33 L18 L19 L20 L21 L22 L23 L24 L25 L26 Q4 Q5 R247 R248 R249 R250 R251 R252 R253 R254 R255 R256 R257 R258 R259 R260 U22 U23 U24 U25 U26 X5
component class "17 - Audio": C145 C146 C147 C148 C149 C150 C151 C152 C153 C154 C155 C156 C157 C158 C159 C160 C161 C162 C163 C164 C165 C166 C167 C168 C169 C170 C171 C172 C173 J37 J38 L32 L33 L34 L35 L36 L37 Q7 Q8 Q9 Q10 R268 R269 R270 R271 R272 R273 R274 R275 R276 R277 R278 R279 R280 R281 R282 R283 R284 R285 U16 U29 U30
component class "18 - I2C, XBee": C174 C175 C176 C177 J39 J40 J41 J42 L38 L39 L40 L41 R286 R287 R288 R289 R290 R291 R292 R293 R294 R295 R296 R297 R298 R299 R300 R301 R302 R303 R304 R305 R306 R307 R308 R309 R310 R311 R312 R313 R333 R334 R335 R336
component class "19 - Expansion connectors, User LEDs, RF signals": D10 D11 D12 J28 J43 J44 J45 J46 J47 J48 J49 J50 J52 J53 Q11 Q12 Q13 R314 R315 R316 R317 R318 R319 R320 R321 SW3 SW4
net class DIFF90: FAA_N FAA_P FT230_USB_N FT230_USB_P G_N G_P NetJ16_2 NetJ16_3 NetL20_1 NetL20_4 NetL21_1 NetL21_4 OTGD_N OTGD_P PCIe/EXPANSION_USB1_D_N PCIe/EXPANSION_USB1_D_P USB_HUB_N USB_HUB_P USB_OTG1_N USB_OTG1_P USB_OTG2_N USB_OTG2_P USB_PCIe_D_N USB_PCIe_D_P USB_RECOVERY_N USB_RECOVERY_P USBH1_D_N USBH1_D_P USBH2_D_N USBH2_D_P XBEE1_USB_D_N XBEE1_USB_D_P XBEE_D_N XBEE_D_P Z_N Z_P
component class "06 - CCIMX8M Nano RF, PCIe": C24 C25 C26 C27 J10 J11 J12 J13 J14 R40 R41 R42 R43 R44 R45 R46 R47 R48 R49 R50 R51 R52 R53 R54 R55 R56 R57 R58 R59 R60 R61 R62 R63 R64 R65 R66 R67 R68 R69 R70 R71 R72 R73 R74 R75 R76 U6
net class DIFF85: FAA_N FAA_P NetR69_1 NetR70_1 NetR71_1 NetR72_1 PCIE_CLK_N PCIE_CLK_P PCIE_RX_N PCIE_RX_P PCIE_SOM_CLK_N PCIE_SOM_CLK_P PCIE_TX_N PCIE_TX_P PCIECLK_N PCIECLK_P PCIETX_N PCIETX_P X_N X_P Y_N Y_P Z_N Z_P
net class DIFF100: ETH1_TXRXA_N ETH1_TXRXA_P ETH1_TXRXB_N ETH1_TXRXB_P ETH1_TXRXC_N ETH1_TXRXC_P ETH1_TXRXD_N ETH1_TXRXD_P HDMI_CLK_N HDMI_CLK_P HDMI_D0_N HDMI_D0_P HDMI_D1_N HDMI_D1_P HDMI_D2_N HDMI_D2_P HDMI_FIL_CLK_N HDMI_FIL_CLK_P HDMI_FIL_D0_N HDMI_FIL_D0_P HDMI_FIL_D1_N HDMI_FIL_D1_P HDMI_FIL_D2_N HDMI_FIL_D2_P LT8912B_CLK_N LT8912B_CLK_P LT8912B_D0_N LT8912B_D0_P LT8912B_D1_N LT8912B_D1_P LT8912B_D2_N LT8912B_D2_P LT8912B_D3_N LT8912B_D3_P LVDS_CLK_N LVDS_CLK_P LVDS_TX0_N LVDS_TX0_P LVDS_TX1_N LVDS_TX1_P LVDS_TX2_N LVDS_TX2_P LVDS_TX3_N LVDS_TX3_P MIPI_CSI_CLK_N MIPI_CSI_CLK_P MIPI_CSI_DATA0_N MIPI_CSI_DATA0_P MIPI_CSI_DATA1_N MIPI_CSI_DATA1_P MIPI_CSI_DATA2_N MIPI_CSI_DATA2_P MIPI_CSI_DATA3_N MIPI_CSI_DATA3_P MIPI_DSI_CLK_N MIPI_DSI_CLK_P MIPI_DSI_DATA0_N MIPI_DSI_DATA0_P MIPI_DSI_DATA1_N MIPI_DSI_DATA1_P MIPI_DSI_DATA2_N MIPI_DSI_DATA2_P MIPI_DSI_DATA3_N MIPI_DSI_DATA3_P MIPI_EXT_CLK_N MIPI_EXT_CLK_P MIPI_EXT_DATA0_N MIPI_EXT_DATA0_P MIPI_EXT_DATA1_N MIPI_EXT_DATA1_P MIPI_EXT_DATA2_N MIPI_EXT_DATA2_P MIPI_EXT_DATA3_N MIPI_EXT_DATA3_P MIPI_SWITCH_CLK_N MIPI_SWITCH_CLK_P MIPI_SWITCH_DATA0_N MIPI_SWITCH_DATA0_P MIPI_SWITCH_DATA1_N MIPI_SWITCH_DATA1_P MIPI_SWITCH_DATA2_N MIPI_SWITCH_DATA2_P MIPI_SWITCH_DATA3_N MIPI_SWITCH_DATA3_P SN65DSI83_CLK_N SN65DSI83_CLK_P SN65DSI83_D0_N SN65DSI83_D0_P SN65DSI83_D1_N SN65DSI83_D1_P SN65DSI83_D2_N SN65DSI83_D2_P SN65DSI83_D3_N SN65DSI83_D3_P
differential pair Z: +Z_P -Z_N
differential pair Y: +Y_P -Y_N
differential pair X: +X_P -X_N
differential pair FAA: +FAA_P -FAA_N
differential pair G: +G_P -G_N
differential pair MIPI_CSI_DATA3: +MIPI_CSI_DATA3_P -MIPI_CSI_DATA3_N
differential pair MIPI_CSI_DATA2: +MIPI_CSI_DATA2_P -MIPI_CSI_DATA2_N
differential pair LVDS_TX3: +LVDS_TX3_P -LVDS_TX3_N
differential pair LVDS_TX2: +LVDS_TX2_P -LVDS_TX2_N
differential pair LVDS_TX1: +LVDS_TX1_P -LVDS_TX1_N
differential pair LVDS_TX0: +LVDS_TX0_P -LVDS_TX0_N
differential pair LVDS_CLK: +LVDS_CLK_P -LVDS_CLK_N
differential pair HDMI_D2: +HDMI_D2_P -HDMI_D2_N
differential pair HDMI_D1: +HDMI_D1_P -HDMI_D1_N
differential pair HDMI_D0: +HDMI_D0_P -HDMI_D0_N
differential pair HDMI_CLK: +HDMI_CLK_P -HDMI_CLK_N
differential pair USB_OTG2: +USB_OTG2_P -USB_OTG2_N
differential pair OTGD: +OTGD_P -OTGD_N
differential pair XBEE1_USB_D: +XBEE1_USB_D_P -XBEE1_USB_D_N
differential pair USB_RECOVERY: +USB_RECOVERY_P -USB_RECOVERY_N
differential pair USB_HUB: +USB_HUB_P -USB_HUB_N
differential pair SN65DSI83_D3: +SN65DSI83_D3_P -SN65DSI83_D3_N
differential pair SN65DSI83_D2: +SN65DSI83_D2_P -SN65DSI83_D2_N
differential pair SN65DSI83_D1: +SN65DSI83_D1_P -SN65DSI83_D1_N
differential pair SN65DSI83_D0: +SN65DSI83_D0_P -SN65DSI83_D0_N
differential pair SN65DSI83_CLK: +SN65DSI83_CLK_P -SN65DSI83_CLK_N
differential pair MIPI_SWITCH_DATA3: +MIPI_SWITCH_DATA3_P -MIPI_SWITCH_DATA3_N
differential pair MIPI_SWITCH_DATA2: +MIPI_SWITCH_DATA2_P -MIPI_SWITCH_DATA2_N
differential pair MIPI_SWITCH_DATA1: +MIPI_SWITCH_DATA1_P -MIPI_SWITCH_DATA1_N
differential pair MIPI_SWITCH_DATA0: +MIPI_SWITCH_DATA0_P -MIPI_SWITCH_DATA0_N
differential pair MIPI_SWITCH_CLK: +MIPI_SWITCH_CLK_P -MIPI_SWITCH_CLK_N
differential pair MIPI_EXT_DATA3: +MIPI_EXT_DATA3_P -MIPI_EXT_DATA3_N
differential pair MIPI_EXT_DATA2: +MIPI_EXT_DATA2_P -MIPI_EXT_DATA2_N
differential pair MIPI_EXT_DATA1: +MIPI_EXT_DATA1_P -MIPI_EXT_DATA1_N
differential pair MIPI_EXT_DATA0: +MIPI_EXT_DATA0_P -MIPI_EXT_DATA0_N
differential pair MIPI_EXT_CLK: +MIPI_EXT_CLK_P -MIPI_EXT_CLK_N
differential pair LT8912B_D3: +LT8912B_D3_P -LT8912B_D3_N
differential pair LT8912B_D2: +LT8912B_D2_P -LT8912B_D2_N
differential pair LT8912B_D1: +LT8912B_D1_P -LT8912B_D1_N
differential pair LT8912B_D0: +LT8912B_D0_P -LT8912B_D0_N
differential pair LT8912B_CLK: +LT8912B_CLK_P -LT8912B_CLK_N
differential pair FT230_USB: +FT230_USB_P -FT230_USB_N
differential pair USB_PCIe_D: +USB_PCIe_D_P -USB_PCIe_D_N
differential pair SPKR: +SPKR_P -SPKR_N
differential pair SPKL: +SPKL_P -SPKL_N
differential pair USBH1_D: +USBH1_D_P -USBH1_D_N
differential pair USBH2_D: +USBH2_D_P -USBH2_D_N
differential pair ETH1_TXRXA: +ETH1_TXRXA_P -ETH1_TXRXA_N
differential pair ETH1_TXRXB: +ETH1_TXRXB_P -ETH1_TXRXB_N
differential pair ETH1_TXRXC: +ETH1_TXRXC_P -ETH1_TXRXC_N
differential pair ETH1_TXRXD: +ETH1_TXRXD_P -ETH1_TXRXD_N
differential pair PCIE_CLK: +PCIE_CLK_P -PCIE_CLK_N
differential pair PCIE_RX: +PCIE_RX_P -PCIE_RX_N
differential pair PCIE_TX: +PCIE_TX_P -PCIE_TX_N
differential pair PCIECLK: +PCIECLK_P -PCIECLK_N
differential pair PCIETX: +PCIETX_P -PCIETX_N
differential pair PCIE_SOM_CLK: +PCIE_SOM_CLK_P -PCIE_SOM_CLK_N
differential pair MIC: +MIC_P -MIC_N
differential pair USB_OTG1: +USB_OTG1_P -USB_OTG1_N
differential pair MIPI_CSI_CLK: +MIPI_CSI_CLK_P -MIPI_CSI_CLK_N
differential pair MIPI_CSI_DATA0: +MIPI_CSI_DATA0_P -MIPI_CSI_DATA0_N
differential pair MIPI_CSI_DATA1: +MIPI_CSI_DATA1_P -MIPI_CSI_DATA1_N
differential pair MIPI_DSI_CLK: +MIPI_DSI_CLK_P -MIPI_DSI_CLK_N
differential pair MIPI_DSI_DATA0: +MIPI_DSI_DATA0_P -MIPI_DSI_DATA0_N
differential pair MIPI_DSI_DATA1: +MIPI_DSI_DATA1_P -MIPI_DSI_DATA1_N
differential pair MIPI_DSI_DATA2: +MIPI_DSI_DATA2_P -MIPI_DSI_DATA2_N
differential pair MIPI_DSI_DATA3: +MIPI_DSI_DATA3_P -MIPI_DSI_DATA3_N

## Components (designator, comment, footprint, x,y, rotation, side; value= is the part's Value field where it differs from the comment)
C1 "22µF" CAPC1608X90N 131.7,44.8 r0 top
C2 "100uF" CAPMP3216X120N 129,42 r0 top
C3 "10uF" CAPC1005X55N 129,43.6 r180 top
C4 "1.0uF" CAPC1005X55N 129,44.8 r180 top
C5 "47pF" CAPC1005X55N 129,49.2 r180 top
C6 "2.2UF" CAPC1608X90N 97.5,60.7 r90 top
C7 "1.0uF" CAPC1005X55N 112.5,56.45 r270 top
C8 "NEXC474Z3.5V10.5X8.5TRF" NEXC474Z3.5V10.5X8.5TRF 90.5,46.5 r270 top locked
C9 "100nF" CAPC1005X55N 103.3,49.4 r180 top
C10 "10uF" CAPC1005X55N 78.8,-46.6 r90 top
C11 "22µF" CAPC1608X90N 113,49.5 r90 top
C12 "22µF" CAPC1608X90N 111.5,49.5 r90 top
C13 "100nF" CAPC1005X55N 110,49.7 r90 top
C14 "100uF" CAPMP3216X120N 73,-47 r90 top
C15 "10uF" CAPC2013X135N 118,44.5 r270 top
C16 "10uF" CAPC2013X135N 116,44.5 r270 top
C17 "10uF" CAPC2013X135N 114,44.5 r270 top
C18 "10uF" CAPC2013X135N 112,44.5 r270 top
C19 "22µF" CAPC1608X90N 74.7,-47.2 r270 top
C20 "100nF" CAPC1005X55N 76,-47.4 r270 top
C21 "47pF" CAPC1005X55N 103.5,50.6 r180 top
C22 "1uF" CAPC1608X90N 103.5,47 r90 top
C23 "15nF" CAPC1005X55N 106,53 r270 top
C24 "0.22uF" CAPC1005X55N 70.8,-20.5 r90 top
C25 "0.22uF" CAPC1005X55N 69.8,-20.5 r90 top
C26 "100nF" CAPC1005X55N 16.5,-49.3 r0 top
C27 "100nF" CAPC1005X55N 16.5,-50.3 r0 top
C28 "100nF" CAPC1005X55N 105,18 r270 top
C29 "2.2UF" CAPC1608X90N -29.5,58 r270 top
C30 "1.0uF" CAPC1005X55N -23.7,57.45 r270 top
C31 "47pF" CAPC1005X55N -19,55.9 r180 top
C32 "47pF" CAPC1005X55N -21,55.9 r0 top
C33 "20pF" CAPC1608X90N -13.5,46.5 r90 top
C34 "20pF" CAPC1608X90N -13.5,49.5 r270 top
C35 "100nF" CAPC1005X55N -15.6,49.2 r180 top
C36 "100nF" CAPC1005X55N -25.3,54 r90 top
C37 "10uF" CAPC1005X55N -16.2,53 r270 top
C38 "100nF" CAPC1005X55N -18,53 r270 top
C39 "100nF" CAPC1005X55N -15.6,47.1 r180 top
C40 "10uF" CAPC1005X55N -28.7,49.3 r90 top
C41 "100nF" CAPC1005X55N -27.5,49.3 r90 top
C42 "100nF" CAPC1005X55N -21.3,42 r180 top
C43 "10uF" CAPC1005X55N -21.5,-55.9 r180 top
C44 "100nF" CAPC1005X55N -21.5,-57 r180 top
C45 "100nF" CAPC1005X55N 58.6,-21.9 r90 top
C46 "100nF" CAPC1005X55N 59.6,-21.9 r90 top
C47 "100uF" CAPMP3216X120N 59.5,-6.5 r0 top
C48 "100uF" CAPMP3216X120N 73.5,-6.5 r0 top
C49 "100uF" CAPMP3216X120N 75,-23 r0 top
C50 "100nF" CAPC1005X55N 55.5,-8 r180 top
C51 "100nF" CAPC1005X55N 67.5,-8 r180 top
C52 "100nF" CAPC1005X55N 77.9,-8 r0 top
C53 "100nF" CAPC1005X55N 72.5,-20 r0 top
C54 "100nF" CAPC1005X55N 74.5,-20 r180 top
C55 "100nF" CAPC1005X55N 8.5,53 r180 top
C56 "100nF" CAPC1005X55N 0,48.9 r180 top
C57 "10pF" CAPC1005X55N 2.6,45.1 r90 top
C58 "10pF" CAPC1005X55N 2.6,47.1 r270 top
C59 "100nF" CAPC1005X55N 76.7,54.5 r90 top
C60 "100nF" CAPC1005X55N -53,-20.4 r180 top
C61 "100nF" CAPC1005X55N -57,-21.6 r0 top
C62 "22pF" CAPC1005X55N -62.1,-34 r90 top
C63 "22pF" CAPC1005X55N -62.1,-32 r270 top
C64 "2.2nF" CAPC1608X90N -49.5,-17.5 r180 top
C65 "100nF" CAPC1005X55N -56.2,-45 r270 top
C66 "10uF" CAPC1005X55N -58.5,-30.9 r0 top
C67 "100nF" CAPC1005X55N -58.5,-32 r0 top
C68 "10uF" CAPC1005X55N -60.4,-27.5 r90 top
C69 "100nF" CAPC1005X55N -54.8,-28 r270 top
C70 "100nF" CAPC1005X55N -54.6,-38.2 r0 top
C71 "1.0uF" CAPC1005X55N -54.6,-39.6 r0 top
C72 "100nF" CAPC1005X55N -45.5,-36 r0 top
C73 "1.0uF" CAPC1005X55N -45.5,-27.6 r0 top
C74 "1.0uF" CAPC1005X55N -58.2,-36.9 r90 top
C75 "100nF" CAPC1005X55N -58.5,-33.8 r0 top
C76 "100nF" CAPC1005X55N -52.6,-38.2 r90 top
C77 "0.22uF" CAPC1005X55N -56.6,-36.9 r90 top
C78 "0.22uF" CAPC1005X55N -53.6,-28 r270 top
C79 "100nF" CAPC1005X55N 41,-47 r270 top
C80 "100nF" CAPC1005X55N 32,-47 r270 top
C81 "100nF" CAPC1005X55N 56.53,57 r0 top
C82 "10uF" CAPC1005X55N 68.6,-48.2 r180 top
C83 "100nF" CAPC1005X55N 68.6,-47 r180 top
C84 "100nF" CAPC1005X55N 68.6,-49.4 r180 top
C85 "22pF" CAPC1005X55N 64.2,-29.3 r180 top
C86 "22pF" CAPC1005X55N 62.2,-29.3 r0 top
C87 "2.2nF" CAPC1608X90N 68.1,-39.5 r0 top
C88 "10uF" CAPC1005X55N 68.1,-44.3 r180 top
C89 "100nF" CAPC1005X55N 58.9,-43.3 r0 top
C90 "100nF" CAPC1005X55N 68.1,-41.9 r180 top
C91 "100nF" CAPC1005X55N 61.2,-32.5 r270 top
C92 "100nF" CAPC1005X55N 56.4,-45.3 r0 top
C93 "100nF" CAPC1005X55N 68.6,-52.2 r180 top
C94 "10uF" CAPC1005X55N 53.5,-37.3 r0 top
C95 "100nF" CAPC1005X55N 56.4,-37.3 r0 top
C96 "100nF" CAPC1005X55N 56.4,-54 r0 top
C97 "10uF" CAPC1005X55N 71.1,-43.1 r180 top
C98 "100nF" CAPC1005X55N 68.1,-43.1 r180 top
C99 "10uF" CAPC1005X55N 71.1,-40.7 r180 top
C100 "100nF" CAPC1005X55N 68.1,-40.7 r180 top
C101 "100nF" CAPC1005X55N 68.6,-53.4 r180 top
C102 "10uF" CAPC1005X55N 71.1,-38.3 r180 top
C103 "100nF" CAPC1005X55N 68.1,-38.3 r180 top
C104 "10uF" CAPC1005X55N 67.6,-32.5 r270 top
C105 "100nF" CAPC1005X55N 65.2,-32.5 r270 top
C106 "10uF" CAPC1005X55N 66.4,-32.5 r270 top
C107 "100nF" CAPC1005X55N 64,-32.5 r270 top
C108 "10uF" CAPC1005X55N 2.6,-38.1 r270 top
C109 "1.0uF" CAPC1005X55N 4,-38.1 r270 top
C110 "100nF" CAPC1005X55N 5,-42.7 r0 top
C111 "1.0uF" CAPC1005X55N 5,-41.5 r180 top
C112 "100nF" CAPC1005X55N -11,-45.3 r0 top
C113 "100nF" CAPC1005X55N -6.7,-38.1 r270 top
C114 "100nF" CAPC1005X55N -11,-46.7 r0 top
C115 "100nF" CAPC1005X55N -0.3,-38.1 r270 top
C116 "100nF" CAPC1005X55N -2.8,-38.1 r270 top
C117 "100nF" CAPC1005X55N 5,-49.3 r180 top
C118 "100nF" CAPC1005X55N -0.3,-53.9 r90 top
C119 "100nF" CAPC1005X55N -4.2,-38.1 r270 top
C120 "100nF" CAPC1005X55N -11,-49.2 r0 top
C121 "100nF" CAPC1005X55N 5,-40.3 r180 top
C122 "100nF" CAPC1005X55N -5.6,-53.9 r90 top
C123 "100nF" CAPC1005X55N -11,-42.3 r0 top
C124 "33pF" CAPC1005X55N 112.5,-34.5 r0 top
C125 "33pF" CAPC1005X55N 112.5,-39.5 r180 top
C126 "1.0uF" CAPC1005X55N 109.5,-48.9 r180 top
C127 "1.0uF" CAPC1005X55N 119.4,-32 r270 top
C128 "10uF" CAPC1005X55N 114.6,-43.5 r270 top
C129 "10uF" CAPC1005X55N 117.1,-43.5 r270 top
C130 "100nF" CAPC1005X55N 115.9,-43.5 r270 top
C131 "100nF" CAPC1005X55N 113.4,-43.5 r270 top
C132 "10uF" CAPC1005X55N 118,-39.3 r0 top
C133 "100nF" CAPC1005X55N 122.9,-43 r90 top
C134 "100nF" CAPC1005X55N 128.5,-39 r180 top
C135 "100nF" CAPC1005X55N 128.5,-36.1 r180 top
C136 "100nF" CAPC1005X55N 118,-35.5 r0 top
C137 "100nF" CAPC1005X55N 123,-32 r270 top
C138 "100nF" CAPC1005X55N 128.5,-37.4 r180 top
C139 "100nF" CAPC1005X55N 118,-38.1 r0 top
C140 "2.2nF" CAPC1608X90N 102.9,-35 r270 top
C141 "1.0uF" CAPC1005X55N -18,-52.4 r0 top
C142 "100nF" CAPC1005X55N -16.55,-54.5 r0 top
C143 "10uF" CAPC1005X55N -16.55,-55.7 r0 top
C144 "100nF" CAPC1005X55N 98.5,-48.7 r0 top
C145 "1.0uF" CAPC1005X55N -61,38.7 r180 top
C146 "1.0uF" CAPC1005X55N -58.8,41.1 r90 top
C147 "1.0uF" CAPC1005X55N -59.9,41.1 r90 top
C148 "10pF" CAPC1005X55N -57.7,41.1 r90 top
C149 "1.0uF" CAPC1005X55N -57.7,43.6 r90 top
C150 "1.0uF" CAPC1005X55N -56.6,43.6 r90 top
C151 "10pF" CAPC1005X55N -52.7,45 r180 top
C152 "10pF" CAPC1005X55N -56.6,41.1 r90 top
C153 "10pF" CAPC1005X55N -55.5,41.1 r90 top
C154 "1.0uF" CAPC1005X55N -55.5,43.6 r90 top
C155 "10pF" CAPC1005X55N -50.5,45 r0 top
C156 "1.0uF" CAPC1005X55N -54.4,43.6 r90 top
C157 "10pF" CAPC1005X55N -54.4,41.1 r90 top
C158 "2.2nF" CAPC1608X90N -56.5,19.8 r0 top
C159 "100nF" CAPC1005X55N -54.4,28.6 r90 top
C160 "1.0uF" CAPC1005X55N -48.2,37.8 r0 top
C161 "100nF" CAPC1005X55N -61,30.9 r0 top
C162 "2.2nF" CAPC1608X90N -51,19.8 r0 top
C163 "1.0uF" CAPC1005X55N -52.4,41 r270 top
C164 "10uF" CAPC1005X55N -49,31 r180 top
C165 "1.0uF" CAPC1005X55N -61,34.2 r180 top
C166 "1.0uF" CAPC1005X55N -61,33.1 r180 top
C167 "1.0uF" CAPC1005X55N -48.2,36.6 r0 top
C168 "1.0uF" CAPC1005X55N -51.3,41 r270 top
C169 "2.2UF" CAPC1608X90N -61,36.4 r0 top
C170 "1.0uF" CAPC1005X55N -61,35.3 r0 top
C171 "10uF" CAPC1005X55N -45.3,33.8 r270 top
C172 "1.0uF" CAPC1005X55N -46.7,33.8 r90 top
C173 "1.0uF" CAPC1005X55N -48.1,33.8 r90 top
C174 "100uF" CAPC3216X190N 135.5,-9 r0 top
C175 "100nF" CAPC1005X55N 136.5,-7 r0 top
C176 "100uF" CAPC3216X190N 135.5,20 r0 top
C177 "100nF" CAPC1005X55N 136.5,22 r0 top
C178 "10uF" CAPC2013X135N 86.5,-45.3 r180 top
C179 "10uF" CAPC2013X135N 86.5,-43.3 r180 top
C180 "100nF" CAPC1005X55N 86,-48.1 r180 top
C181 "100nF" CAPC1005X55N 86,-46.9 r180 top
C182 "100nF" CAPC1005X55N -57.4,-45 r270 top
C183 "100nF" CAPC1005X55N -58.6,-45 r270 top
C184 "100nF" CAPC1005X55N -59.8,-45 r270 top
C185 "1.0uF" CAPC1005X55N 95,54.3 r180 top
C186 "10uF" CAPC1005X55N -30.9,-36.8 r180 top
C187 "100uF" CAPMP3216X120N -30.1,-41 r180 top
C188 "22µF" CAPC1608X90N -28.5,-38.5 r270 top
C189 "100nF" CAPC1005X55N -30.5,-39.5 r0 top
C190 "10uF" CAPC1005X55N -36.9,-36.8 r180 top
C191 "100uF" CAPMP3216X120N -36,-41 r180 top
C192 "22µF" CAPC1608X90N -34.5,-38.5 r270 top
C193 "100nF" CAPC1005X55N -36.5,-39.5 r0 top
C194 "1.0uF" CAPC1005X55N 91,-44.4 r0 top
C195 "100nF" CAPC1005X55N 92.45,-46.5 r0 top
C196 "10uF" CAPC1005X55N 92.45,-47.7 r0 top
C197 "100nF" CAPC1005X55N 5.69,39.7 r90 top
C198 "100nF" CAPC1005X55N 1.3,39.7 r270 top
C199 "1.0uF" CAPC1005X55N 65.5,0.5 r270 top
C200 "2.2UF" CAPC1608X90N 62.5,-1.5 r180 top
D1 "597-3301-507F" LEDM3020X130N 88,60.5 r270 top
D2 "DB2J31400L" SODFL2513X80N 101.5,57 r270 top
D3 "BAT54CWT1G" SOT65P210X100-3AN 99.5,60.5 r0 top
D4 "597-3301-507F" LEDM3020X130N -31,38.5 r0 top
D5 "597-3401-507F" LEDM3020X130N -25,38.5 r0 top
D6 "597-3301-507F" LEDM3020X130N -13,38.5 r0 top
D7 "597-3401-507F" LEDM3020X130N -19,38.5 r0 top
D8 "BAT54_D87Z" SOT95P240X110_AXK-3N 55.4,-47.5 r270 top
D9 "ESD9B5.0ST5G" SODFL1006X43N12 -17.3,-58.3 r270 top
D10 "597-3401-507F" LEDM3020X130N 68,60.5 r270 top
D11 "597-3301-507F" LEDM3020X130N 72,60.5 r270 top
D12 "597-3021-507F" LEDM3020X130N 64,60.5 r270 top
D13 "ESD9B3.3ST5G" SODFL1006X43AN12 82.7,-45 r270 top
D14 "ESD9B3.3ST5G" SODFL1006X43AN12 81.6,-45 r270 top
D15 "ESD9B3.3ST5G" SODFL1006X43AN12 83.8,-45 r270 top
D16 "ESD9B3.3ST5G" SODFL1006X43AN12 80.4,-45 r270 top
D17 "ESD9B3.3ST5G" SODFL1006X43AN12 1.175,61.5 r180 top
D18 "ESD9B3.3ST5G" SODFL1006X43AN12 -1.195,61.5 r0 top
D19 "ESD9B3.3ST5G" SODFL1006X43AN12 81.8,61.5 r180 top
D20 "ESD9B3.3ST5G" SODFL1006X43AN12 78.2,61.5 r0 top
D21 "ESD9B5.0ST5G" SODFL1006X43N12 98.15,-59 r0 top
FIDUCIAL1 "40mil FID" FIDUCIAL_40MIL_ROUND -62.5,63 r90 top
FIDUCIAL2 "40mil FID" FIDUCIAL_40MIL_ROUND 132.5,-63 r90 top
FIDUCIAL3 "40mil FID" FIDUCIAL_40MIL_ROUND 132.5,63 r90 top
FIDUCIAL4 "40mil FID" FIDUCIAL_40MIL_ROUND -62.5,63 r90 bottom
FIDUCIAL5 "40mil FID" FIDUCIAL_40MIL_ROUND 132.5,-63 r90 bottom
FIDUCIAL6 "40mil FID" FIDUCIAL_40MIL_ROUND 132.5,63 r90 bottom
FIL1 "NFE31PT220R1E9L" FIL_NFE31P 137.5,45 r270 top
H1 "125mil" MH_185_125_NP 136.25,-61.25 r0 top
H2 "125mil" MH_185_125_NP 136.25,61.25 r0 top
H3 "125mil" MH_185_125_NP -66.25,61.25 r0 top
H4 "125mil" MH_185_125_NP -66.25,-61.25 r0 top
J1 "CSCD443CCS011B00G" CONN_CSCD443CCS011B00G 125,52 r270 top locked
J2 "640456-2" TE_640456-2 136,52 r90 top locked
J3 "1x2" FCI_68002-102HLF 94,61.5 r0 top locked
J4 "1x2P" MOLEX_53047-0210_FLEX 105,62.5 r0 top
J5 "640456-2" TE_640456-2 115,61.5 r180 top
J6 "1x2" FCI_68002-102HLF 50,-26 r180 top
J7 "1x2" FCI_68002-102HLF -31,-45 r90 top
J8 "1x2" FCI_68002-102HLF -37,-45 r90 top
J9 "1x2" FCI_68002-102HLF 88,0 r180 top locked
J10 "U.FL-R-SMT(01)" HIROSE_U.FL-R-SMT(01) -65,-40 r0 top
J11 "SMA A700T" "BOBBINTRON_SMA A700T" -65,-51 r180 top locked
J12 "FTSH-105-01-F-DV" SAMTEC_FTSH-105-01-F-DV -66,21.5 r180 top
J13 "U.FL-R-SMT(01)" HIROSE_U.FL-R-SMT(01) -65,40 r180 top
J14 "SMA A700T" "BOBBINTRON_SMA A700T" -65,51 r180 top locked
J15 "U.FL-R-SMT(01)" HIROSE_U.FL-R-SMT(01) 135,-40 r0 top
J16 "KMMX-ABSMT5SG-30TR" KYCON_KMMX-ABSMT5 -20,63.5 r180 top locked
J17 "0022284060" MOLEX_0022284060 -32,56 r90 top
J18 "500873-0806" MOLEX_500873-0806 -28,-59.5 r180 top locked
J19 "PCIe Minicard" FOXCONN_AS0B221-S68Q-7H 66.5,-14 r0 top locked
J20 "FTSH-105-01-F-DV" SAMTEC_FTSH-105-01-F-DV 18,50 r270 top locked
J21 "78727-0001" MOLEX_78727-0001 82,-63.5 r270 top locked
J22 "FTSH-105-01-F-DV" SAMTEC_FTSH-105-01-F-DV 30,50 r270 top locked
J23 "1x2" FCI_68002-102HLF 0.625,58 r0 top
J24 "1x4P" HDRV4W64P254_4X1_1016X248H1067 0,63.5 r0 top locked
J25 "1x2" FCI_68002-102HLF 80.625,58 r0 top
J26 "1x4P" HDRV4W64P254_4X1_1016X248H1067 80,63.5 r0 top locked
J27 "RJ45" XMULTIPLE_XMG-J1B211 -50.5,-57.048 r0 top locked
J28 "0022284060" MOLEX_0022284060 52,63.5 r180 top locked
J29 "SFW15S-2STE1LF" FCI_SFW15S-2STE1LF 50,53.5 r180 top locked
J30 "SFW15S-2STE1LF" FCI_SFW15S-2STE1LF 36,-61.5 r0 top locked
J31 "KDMIX-NS1-NS-B" KYCON_KDMIX 61,-62.8 r0 top locked
J32 "DF14A-20P-1.25H(25)" HIROSE_DF14A-20P-1.25H 8,-60.5 r180 top locked
J33 "KUSBX-AS2N" KYCON_KUSBX-AS2N_FLEX 120,-57.5 r0 top locked
J34 "KMMX-ABSMT5SG-30TR" KYCON_KMMX-ABSMT5 -14,-63.5 r0 top locked
J35 "KMMX-ABSMT5SG-30TR" KYCON_KMMX-ABSMT5 100,-63 r0 top locked
J36 "1x2" FCI_68002-102HLF 96,-52 r90 top
J37 "MIC" CUI_SJ1-3533N -55.5,57.5 r270 top
J38 "HP" CUI_SJ1-3533N -46,57.5 r270 top
J39 "SMM-110-02-F-S-P-TR" SAMTEC_SMM-110-02-F-S 128,-3.5 r180 top locked
J40 "SMM-110-02-F-S-P-TR" SAMTEC_SMM-110-02-F-S 128,-25.5 r180 top locked
J41 "SMM-110-02-F-S-P-TR" SAMTEC_SMM-110-02-F-S 128,25.5 r180 top locked
J42 "SMM-110-02-F-S-P-TR" SAMTEC_SMM-110-02-F-S 128,3.5 r180 top locked
J43 "0022284060" MOLEX_0022284060 18,63.5 r180 top locked
J44 "5X2POS" MOLEX_87914-1016 -67,8 r90 top
J45 "5X2POS" MOLEX_87914-1016 92,10 r180 top locked
J46 "0022284060" MOLEX_0022284060 99,0 r180 top locked
J47 "TSW-112-26-L-D" SAMTEC_TSW-112-26-L-D 103,37 r180 top locked
J48 "5X2POS" MOLEX_87914-1016 96,-30 r180 top locked
J49 "TSW-110-26-L-D" SAMTEC_TSW-110-26-L-D -67,-13 r90 top
J50 "8 PIN HT SR HEADER .100\"" SAMTEC_TSW-108-07-X-S 96,-20 r180 top locked
J51 "SMA A700T" "BOBBINTRON_SMA A700T" 135,-51 r0 top locked
J52 "5X2POS" MOLEX_87914-1016 96,-10 r180 top
J53 "5X2POS" MOLEX_87914-1016 -38,57 r270 top locked
L1 "4.7uH" IND_DG6045C 107.5,44 r0 top locked
L2 "220" INDC2013X110N -18.3,58 r270 top
L3 "744231121" FIL_DLW21H -20,58 r270 top
L4 "220" INDC2013X110N -21.8,58 r270 top
L5 "4.7uH" INDC2520X100L60N -58.5,-28 r90 top
L6 "120" INDC1005X60N -54.6,-40.8 r0 top
L7 "120" INDC1005X60N -53.7,-25 r90 top
L8 "DLP11SN900" FIL_DLP11S 65,-45 r270 top
L9 "DLP11SN900" FIL_DLP11S 63.5,-45 r270 top
L10 "DLP11SN900" FIL_DLP11S 62,-45 r270 top
L11 "DLP11SN900" FIL_DLP11S 60.5,-45 r270 top
L12 "DLP11SN900" FIL_DLP11S -2,-55.5 r270 top
L13 "DLP11SN900" FIL_DLP11S 1.75,-55.5 r270 top
L14 "DLP11SN900" FIL_DLP11S 5.5,-55.5 r270 top locked
L15 "DLP11SN900" FIL_DLP11S 9.25,-55.5 r270 top locked
L16 "DLP11SN900" FIL_DLP11S 13,-55.5 r270 top locked
L17 "220" INDC2013X110N 20.2,-55 r270 top
L18 "220" INDC2013X110N 116.5,-46.5 r90 top
L19 "220" INDC2013X110N 114,-46.5 r90 top
L20 "744231121" FIL_DLW21H 119.4,-44 r270 top locked
L21 "744231121" FIL_DLW21H 121,-44 r270 top locked
L22 "220" INDC2013X110N 115.4,-32 r90 top
L23 "220" INDC2013X110N 123.5,-46.5 r270 top
L24 "220" INDC2013X110N 126,-46.5 r270 top
L25 "744231121" FIL_DLW21H 114,-14 r90 top locked
L26 "744231121" FIL_DLW21H 120,-15 r90 top locked
L27 "220" INDC2013X110N -15.8,-58 r90 top
L28 "744231121" FIL_DLW21H -14,-58 r270 top locked
L29 "220" INDC2013X110N -12.2,-58 r270 top
L30 "220" INDC2013X110N 97.6,-57 r180 top
L31 "220" INDC2013X110N 101.3,-57.4 r90 top
L32 "1.8K" INDC1005X60N -58.8,43.6 r270 top
L33 "1.8K" INDC1005X60N -59.9,43.6 r270 top
L34 "1.8K" INDC1005X60N -57.7,45.6 r270 top
L35 "1.8K" INDC1005X60N -56.6,45.6 r270 top
L36 "1.8K" INDC1005X60N -55.5,45.6 r270 top
L37 "1.8K" INDC1005X60N -54.4,45.6 r270 top
L38 "220" INDC2013X110N 136,-11 r0 top
L39 "220" INDC2013X110N 137.7,-11 r180 top
L40 "220" INDC2013X110N 136,18 r0 top
L41 "220" INDC2013X110N 137.7,18 r180 top
Q1 "2N7002T" SOTFL50P160X80_GSD-3N 88,57 r0 top
Q2 "2N7002T" SOTFL50P160X80_GSD-3N -49.5,-9.5 r270 top
Q3 "NTR4003NT1G" SOT95P240X110_GSD-3N -49.5,-21.5 r180 top
Q4 "2N7002T" SOTFL50P160X80_GSD-3N 95,-35 r0 top
Q5 "NTR4003NT1G" SOT95P240X110_GSD-3N 106.9,-35 r270 top
Q6 "2N7002T" SOTFL50P160X80_GSD-3N 95,-46.5 r90 top
Q7 "2N7002T" SOTFL50P160X80_GSD-3N -56.5,11.5 r90 top
Q8 "NTR4003NT1G" SOT95P240X110_GSD-3N -56.5,23.5 r0 top
Q9 "NTR4003NT1G" SOT95P240X110_GSD-3N -51,10.5 r90 top
Q10 "NTR4003NT1G" SOT95P240X110_GSD-3N -51,23.5 r0 top
Q11 "2N7002T" SOTFL50P160X80_GSD-3N 72,57 r0 top
Q12 "2N7002T" SOTFL50P160X80_GSD-3N 68,57 r0 top
Q13 "2N7002T" SOTFL50P160X80_GSD-3N 64,57 r0 top
R1 "47K" RESC1005X40N 37.1,44.5 r90 top
R2 "0" RESC1005X40N 38.3,44.5 r270 top
R3 "100K" RESC1005X40N 39.5,41.5 r270 top
R4 "0" RESC1005X40N 39.5,44.5 r270 top
R5 "0" RESC1005X40N 37.1,41.5 r270 top
R6 "0" RESC1005X40N 38.3,41.5 r270 top
R7 "10.0K" RESC1005X40N 132.7,47.2 r270 top
R8 "0" RESC1005X40N 108.8,9.52 r90 top
R9 "100K" RESC1005X40N 108.8,10.48 r90 top
R10 "220" RESC1005X40N 88,63.5 r0 top
R11 "100K" RESC1005X40N 88,54.9 r0 top
R12 "0" RESC1609X55N 101.5,60.5 r270 top
R13 "0" RESC1609X55N 94,63.5 r180 top
R14 "12K" RESC1609X55N 107.1,57 r270 top
R15 "2.2K" RESC1005X40N 98.9,58 r90 top
R16 "10.0" RESC1005X40N 93,57 r90 top
R17 "20K" RESC1609X55N 105.5,57 r90 top
R18 "0" RESC1609X55N 102,47 r270 top
R19 "0" RESC1609X55N 71,-47 r90 top
R20 "100K" RESC1005X40N 107.2,53 r270 top
R21 "100K" RESC1005X40N 100.6,47 r270 top
R22 "0" RESC1005X40N 99.4,47 r90 top
R23 "470K" RESC1005X40N 109.6,53 r90 top
R24 "53.6k" RESC1609X55N 103.5,52 r180 top
R25 "100K" RESC1005X40N 76.8,-45.3 r180 top
R26 "470K" RESC1005X40N 108.4,53 r270 top
R27 "12K" RESC1609X55N 103.5,53.6 r0 top
R28 "0" RESC1609X55N 50,-28 r180 top
R29 "0" RESC1609X55N 45,-12.5 r180 top
R30 "0" RESC1609X55N 45,-14.5 r180 top
R31 "0" RESC1609X55N -29,-45 r270 top
R32 "0" RESC1609X55N -35,-45 r270 top
R33 "0" RESC1609X55N 45,-8.5 r180 top
R34 "0" RESC1609X55N 45,-10.5 r180 top
R35 "0" RESC1609X55N -13,-38 r90 top
R36 "0" RESC1005X40N 5.5,-38 r90 top
R37 "0" RESC1005X40N -45,-11.6 r0 top
R38 "0" RESC1005X40N -45,-10.4 r0 top
R39 "0" RESC1005X40N 13.6,38.5 r270 top
R40 "0" RESC1005X40N -60,-3.5 r180 top
R41 "0" RESC1005X40N -60,-2 r180 top
R42 "10.0K" RESC1005X40N -61,23 r0 top
R43 "0" RESC1005X40N -60,-21.5 r180 top
R44 "0" RESC1005X40N -60,-18.5 r180 top
R45 "0" RESC1005X40N -60,-15.5 r180 top
R46 "10.0K" RESC1005X40N -61,21.5 r0 top
R47 "0" RESC1005X40N -60,-12.5 r180 top
R48 "0" RESC1005X40N -60,-9.5 r180 top
R49 "0" RESC1005X40N -60,-8 r180 top
R50 "0" RESC1005X40N -60,-6.5 r180 top
R51 "0" RESC1005X40N -65,-45 r90 top
R52 "0" RESC1005X40N -60,-5 r180 top
R53 "10.0K" RESC1005X40N -44.98,5 r180 top
R54 "0" RESC1005X40N -64.5,-43.5 r180 top
R55 "0" RESC1005X40N -64.5,-46.5 r180 top
R56 "0" RESC1005X40N -60,-20 r180 top
R57 "0" RESC1005X40N -60,-17 r180 top
R58 "0" RESC1005X40N -60,-11 r180 top
R59 "0" RESC1005X40N -60,-14 r180 top
R60 "0" RESC1005X40N -65,45 r270 top
R61 "0" RESC1005X40N -64.5,43.5 r180 top
R62 "0" RESC1005X40N -64.5,46.5 r180 top
R63 "0" RESC1609X55N 17.5,-41.1 r90 top
R64 "0" RESC1609X55N 18.9,-41.1 r90 top
R65 "0" RESC1609X55N 71,-22.8 r270 top
R66 "0" RESC1609X55N 69.6,-22.8 r270 top
R67 "0" RESC1609X55N 67.8,-20.8 r270 top
R68 "0" RESC1609X55N 66.4,-20.8 r270 top
R69 "22" RESC1005X40N 17.7,-46.1 r90 top
R70 "22" RESC1005X40N 18.7,-46.1 r90 top
R71 "22" RESC1005X40N 22.3,-46.1 r90 top
R72 "22" RESC1005X40N 21.3,-46.1 r90 top
R73 "49.9" RESC1005X40N 22.7,-44.5 r180 top
R74 "49.9" RESC1005X40N 20.9,-44.5 r0 top
R75 "49.9" RESC1005X40N 17.3,-44.5 r180 top
R76 "49.9" RESC1005X40N 19.1,-44.5 r0 top
R77 "4.7K" RESC1005X40N 123,38.7 r180 top
R78 "0" RESC1005X40N 123,37.5 r180 top
R79 "4.7K" RESC1005X40N 123,35 r180 top
R80 "100K" RESC1005X40N 123,36.2 r0 top
R81 "4.7K" RESC1005X40N 16,38.5 r270 top
R82 "100K" RESC1005X40N 14.8,38.5 r270 top
R83 "4.7K" RESC1005X40N 18.5,38.5 r270 top
R84 "100K" RESC1005X40N 17.3,38.5 r270 top
R85 "4.7K" RESC1005X40N 108.8,30.52 r90 top
R86 "4.7K" RESC1005X40N 106.4,30.52 r90 top
R87 "4.7K" RESC1005X40N 104,30.52 r90 top
R88 "4.7K" RESC1005X40N 101.6,30.52 r90 top
R89 "4.7K" RESC1005X40N 99.2,30.52 r90 top
R90 "4.7K" RESC1005X40N 96.8,30.52 r90 top
R91 "4.7K" RESC1005X40N 94.4,30.52 r90 top
R92 "4.7K" RESC1005X40N 92,30.52 r90 top
R93 "4.7K" RESC1005X40N 110,30.52 r90 top
R94 "4.7K" RESC1005X40N 107.6,30.52 r90 top
R95 "4.7K" RESC1005X40N 105.2,30.52 r90 top
R96 "4.7K" RESC1005X40N 102.8,30.52 r90 top
R97 "4.7K" RESC1005X40N 100.4,30.52 r90 top
R98 "4.7K" RESC1005X40N 98,30.52 r90 top
R99 "4.7K" RESC1005X40N 95.6,30.52 r90 top
R100 "4.7K" RESC1005X40N 93.2,30.52 r90 top
R101 "100K" RESC1005X40N 108.8,31.48 r90 top
R102 "100K" RESC1005X40N 106.4,31.48 r90 top
R103 "100K" RESC1005X40N 104,31.48 r90 top
R104 "100K" RESC1005X40N 101.6,31.48 r90 top
R105 "100K" RESC1005X40N 99.2,31.48 r90 top
R106 "100K" RESC1005X40N 96.8,31.48 r90 top
R107 "100K" RESC1005X40N 94.4,31.48 r90 top
R108 "100K" RESC1005X40N 92,31.48 r90 top
R109 "100K" RESC1005X40N 110,31.48 r90 top
R110 "100K" RESC1005X40N 107.6,31.48 r90 top
R111 "100K" RESC1005X40N 105.2,31.48 r90 top
R112 "100K" RESC1005X40N 102.8,31.48 r90 top
R113 "100K" RESC1005X40N 100.4,31.48 r90 top
R114 "100K" RESC1005X40N 98,31.48 r90 top
R115 "100K" RESC1005X40N 95.6,31.48 r90 top
R116 "100K" RESC1005X40N 93.2,31.48 r90 top
R117 "10.0K" RESC1005X40N 105,16 r270 top
R118 "4.7K" RESC1005X40N 107.6,9.52 r90 top
R119 "4.7K" RESC1005X40N 105.2,9.52 r90 top
R120 "4.7K" RESC1005X40N 101.6,9.52 r90 top
R121 "4.7K" RESC1005X40N 106.4,9.52 r90 top
R122 "4.7K" RESC1005X40N 104,9.52 r90 top
R123 "4.7K" RESC1005X40N 102.8,9.52 r90 top
R124 "4.7K" RESC1005X40N 100.4,9.52 r90 top
R125 "0" RESC1005X40N 107.6,10.48 r270 top
R126 "0" RESC1005X40N 105.2,10.48 r270 top
R127 "0" RESC1005X40N 101.6,10.48 r270 top
R128 "0" RESC1005X40N 106.4,10.48 r270 top
R129 "0" RESC1005X40N 104,10.48 r270 top
R130 "0" RESC1005X40N 102.8,10.48 r270 top
R131 "0" RESC1005X40N 100.4,10.48 r270 top
R132 "0" RESC1609X55N -14.2,57 r180 top
R133 "0" RESC1609X55N -27.9,52.5 r270 top
R134 "0" RESC1609X55N -26.5,52.5 r270 top
R135 "0" RESC1609X55N -15.8,57 r0 top
R136 "0" RESC1609X55N -29.5,52.5 r270 top
R137 "12K" RESC1609X55N -27.8,60.4 r180 top
R138 "22" RESC1005X40N -19.5,54.5 r270 top
R139 "22" RESC1005X40N -20.5,54.5 r270 top
R140 "20K" RESC1609X55N -27.8,62 r0 top
R141 "0" RESC1609X55N -29,45 r180 top
R142 "0" RESC1609X55N -29,46.5 r180 top
R143 "120" RESC1005X40N -34,38.5 r270 top
R144 "120" RESC1005X40N -28,38.5 r270 top
R145 "1.5K" RESC1005X40N -22.5,54 r90 top
R146 "0" RESC1609X55N -29,41.5 r180 top
R147 "0" RESC1609X55N -29,43 r180 top
R148 "120" RESC1005X40N -16,38.5 r270 top
R149 "470R 1%" RESC0603X28N -16.2,50.7 r270 top
R150 "120" RESC1005X40N -22,38.5 r270 top
R151 "0" RESC1609X55N -6.8,39 r180 top
R152 "0" RESC1609X55N -5.2,39 r0 top
R153 "0" RESC1609X55N -6.8,37.5 r180 top
R154 "0" RESC1609X55N -5.2,37.5 r0 top
R155 "0" RESC1005X40N -21.5,-53.7 r0 top
R156 "0" RESC1005X40N -21.5,-54.8 r0 top
R157 "10.0K" RESC1005X40N -26.2,-46.5 r270 top
R158 "100K" RESC1005X40N -25,-46.5 r90 top
R159 "10.0K" RESC1005X40N -23.8,-46.5 r270 top
R160 "10.0K" RESC1005X40N 54.7,-20.5 r270 top
R161 "22" RESC1005X40N -16,-38 r225 top
R162 "49.9" RESC1005X40N 60,-20.4 r180 top
R163 "49.9" RESC1005X40N 58.2,-20.4 r0 top
R164 "10.0K" RESC1005X40N 12,38.5 r270 top
R165 "0" RESC1005X40N 4,55.5 r0 top
R166 "120" RESC1005X40N 1.1,60 r0 top
R167 "0" RESC1005X40N -4,54 r0 top
R168 "1.0K" RESC1005X40N -4,55.5 r0 top
R169 "120" RESC1005X40N 81.1,60 r0 top
R170 "0" RESC1609X55N -52,-15 r270 top
R171 "10.0K" RESC1005X40N -50,-12.3 r0 top
R172 "120" RESC1005X40N -50,-19 r0 top
R173 "10.0K" RESC1005X40N -57,-20.4 r0 top
R174 "100K" RESC1005X40N -50,-11.1 r0 top
R175 "12K" RESC1609X55N -60.5,-33 r90 top
R176 "120" RESC1005X40N -45.5,-38.5 r0 top
R177 "10.0K" RESC1005X40N 77.6,48.7 r180 top
R178 "1.0K" RESC1005X40N -55,-25 r90 top
R179 "0" RESC1005X40N -56.6,-28 r270 top
R180 "0" RESC3225X60N -40,-50.1 r270 top
R181 "10.0K" RESC1005X40N -51.2,-25 r270 top
R182 "120" RESC1005X40N -45.5,-40.9 r0 top
R183 "10.0K" RESC1005X40N -50,-25 r90 top
R184 "10.0K" RESC1005X40N -16.1,-43 r270 top
R185 "4.7K" RESC1005X40N -52.4,-25 r270 top
R186 "10.0K" RESC1005X40N -45.52,-31.2 r0 top
R187 "10.0K" RESC1005X40N -45.52,-32.4 r0 top
R188 "10.0K" RESC1005X40N -45.52,-39.7 r0 top
R189 "10.0K" RESC1005X40N -45.52,-30 r0 top
R190 "10.0K" RESC1005X40N -45.52,-33.6 r0 top
R191 "10.0K" RESC1005X40N -45.52,-28.8 r0 top
R192 "10.0K" RESC1005X40N -45.52,-34.8 r0 top
R193 "10.0K" RESC1005X40N -45.52,-37.3 r0 top
R194 "2.37K" RESC1005X40N -59.3,-36.9 r90 top
R195 "10.0K" RESC1005X40N -46.48,-31.2 r0 top
R196 "10.0K" RESC1005X40N -46.48,-32.4 r0 top
R197 "10.0K" RESC1005X40N -46.48,-39.7 r0 top
R198 "10.0K" RESC1005X40N -46.48,-30 r0 top
R199 "10.0K" RESC1005X40N -46.48,-33.6 r0 top
R200 "10.0K" RESC1005X40N -46.48,-28.8 r0 top
R201 "10.0K" RESC1005X40N -46.48,-34.8 r0 top
R202 "10.0K" RESC1005X40N -46.48,-37.3 r0 top
R203 "0" RESC1609X55N 43.5,-52.7 r90 top
R204 "0" RESC1609X55N 33.5,-52.7 r90 top
R205 "0" RESC1609X55N 33.5,-54.3 r270 top locked
R206 "0" RESC1609X55N 35.3,-52.7 r90 top
R207 "0" RESC1609X55N 35.3,-54.3 r270 top locked
R208 "0" RESC1609X55N 26.9,-52.7 r90 top
R209 "0" RESC1609X55N 26.9,-54.3 r270 top
R210 "0" RESC1609X55N 28.7,-52.7 r90 top
R211 "0" RESC1609X55N 28.7,-54.3 r270 top
R212 "0" RESC1609X55N 30.2,-52.7 r90 top
R213 "0" RESC1609X55N 30.2,-54.3 r270 top
R214 "0" RESC1609X55N 32,-52.7 r90 top
R215 "0" RESC1609X55N 32,-54.3 r270 top locked
R216 "0" RESC1609X55N 36.8,-52.7 r90 top
R217 "0" RESC1609X55N 36.8,-54.3 r270 top
R218 "0" RESC1609X55N 38.6,-52.7 r90 top
R219 "0" RESC1609X55N 38.6,-54.3 r270 top
R220 "0" RESC1609X55N 40.1,-52.7 r90 top
R221 "0" RESC1609X55N 40.1,-54.3 r270 top
R222 "0" RESC1609X55N 41.9,-52.7 r90 top
R223 "0" RESC1609X55N 41.9,-54.3 r270 top
R224 "0" RESC1005X40N 68.6,-50.6 r0 top
R225 "10.0K" RESC1005X40N 59,-32.5 r270 top
R226 "27K" RESC1005X40N 56.4,-49.6 r0 top
R227 "1M_1%" RESC1005X40N 63.2,-30.5 r0 top
R228 "5.97K" RESC1005X40N 56.4,-40.5 r180 top
R229 "0" RESC1005X40N 62.4,-32.5 r270 top
R230 "15.0k" RESC1005X40N 56.4,-52.9 r0 top
R231 "47K" RESC1005X40N 56.4,-44.1 r0 top
R232 "0" RESC1005X40N 56.4,-42.9 r180 top
R233 "4.7K" RESC1005X40N 56.4,-50.7 r0 top
R234 "4.7K" RESC1005X40N 56.4,-51.8 r0 top
R235 "0" RESC1609X55N -47.8,27.5 r180 top
R236 "0" RESC1609X55N -46.2,27.5 r0 top
R237 "0" RESC1609X55N -47.8,23.5 r180 top
R238 "0" RESC1609X55N -47.8,25.5 r180 top
R239 "0" RESC1609X55N -46.2,25.5 r0 top
R240 "0" RESC1609X55N -47.8,29.5 r180 top
R241 "0" RESC1609X55N -46.2,29.5 r0 top
R242 "4.7K" RESC1005X40N 5,-50.5 r0 top
R243 "10.0K" RESC1005X40N -6.8,-53.9 r90 top
R244 "10.0K" RESC1005X40N 18.6,-55.5 r270 top
R245 "4.7K" RESC1005X40N -11,-51.6 r180 top
R246 "4.7K" RESC1005X40N -11,-50.4 r0 top
R247 "10.0K" RESC1005X40N 110.2,-39.5 r90 top
R248 "10.0K" RESC1005X40N 108.8,-39.5 r90 top
R249 "1M_1%" RESC1005X40N 114.6,-37.5 r270 top
R250 "10.0K" RESC1005X40N 118.2,-32 r90 top
R251 "47K" RESC1005X40N 118,-34.3 r180 top
R252 "10.0K" RESC1005X40N 117,-32 r270 top
R253 "12K" RESC1609X55N 118,-40.5 r180 top
R254 "47K" RESC1005X40N 124.2,-32 r270 top
R255 "47K" RESC1005X40N 121.8,-32 r270 top
R256 "47K" RESC1005X40N 120.6,-32 r270 top
R257 "0" RESC1609X55N 100.4,-37.5 r0 top
R258 "10.0K" RESC1005X40N 97.8,-35.5 r90 top
R259 "120" RESC1005X40N 104.4,-35.5 r90 top
R260 "100K" RESC1005X40N 96.5,-35.5 r90 top
R261 "10.0K" RESC1005X40N -17.3,-43 r90 top
R262 "10.0K" RESC1005X40N 95,-45 r180 top
R263 "0" RESC1609X55N 100.9,-53 r270 top
R264 "1.0K" RESC1005X40N 95,-48 r0 top
R265 "0" RESC1609X55N 100.9,-51.4 r90 top
R266 "0" RESC1609X55N 99.1,-53 r270 top
R267 "0" RESC1609X55N 99.1,-51.4 r90 top
R268 "10.0K" RESC1005X40N -61,29.8 r0 top
R269 "0" RESC1005X40N -56.7,28.6 r90 top
R270 "0" RESC1005X40N -55.6,28.6 r90 top
R271 "0" RESC1005X40N -61,32 r0 top
R272 "0" RESC1005X40N -57.8,28.6 r90 top
R273 "2.2K" RESC1005X40N -61,37.5 r180 top
R274 "0" RESC1005X40N -58.8,45.6 r90 top
R275 "0" RESC1005X40N -59.9,45.6 r90 top
R276 "0" RESC1005X40N -52.2,46.5 r90 top
R277 "0" RESC1005X40N -51,46.5 r90 top
R278 "0" RESC1609X55N -54,17 r90 top
R279 "10.0K" RESC1005X40N -56,14.3 r180 top
R280 "120" RESC1005X40N -56,21.2 r180 top
R281 "100K" RESC1005X40N -56,13.1 r180 top
R282 "0" RESC1609X55N -48.5,17 r90 top
R283 "10.0K" RESC1005X40N -50.5,14.3 r180 top
R284 "120" RESC1005X40N -50.5,21.2 r180 top
R285 "100K" RESC1005X40N -50.5,13.1 r180 top
R286 "0" RESC1005X40N 13.5,-38 r90 top
R287 "0" RESC1005X40N 13.5,-41 r270 top
R288 "0" RESC1005X40N 65.5,23.5 r270 top
R289 "0" RESC1005X40N 65.5,26.5 r90 top
R290 "0" RESC1005X40N 67,23.5 r270 top
R291 "2.2K" RESC1005X40N 64,23.5 r270 top
R292 "2.2K" RESC1005X40N 64,26.5 r90 top
R293 "0" RESC1005X40N 67,26.5 r90 top
R294 "2.2K" RESC1005X40N 10.5,-38 r90 top
R295 "2.2K" RESC1005X40N 10.5,-41 r270 top
R296 "0" RESC1005X40N 68.5,23.5 r270 top
R297 "0" RESC1005X40N 12,-38 r90 top
R298 "0" RESC1005X40N 68.5,26.5 r90 top
R299 "0" RESC1005X40N 12,-41 r270 top
R300 "0" RESC1005X40N 70,23.5 r270 top
R301 "0" RESC1005X40N 15,-38 r90 top
R302 "0" RESC1005X40N 70,26.5 r90 top
R303 "0" RESC1005X40N 15,-41 r270 top
R304 "0" RESC1005X40N 130.3,-8.5 r90 top locked
R305 "0" RESC1005X40N 127,-8.5 r90 top locked
R306 "0" RESC1005X40N 125,-20.5 r90 top
R307 "10.0K" RESC1005X40N 129.5,-20 r0 top
R308 "0" RESC1005X40N 119,-20.5 r90 top
R309 "0" RESC1005X40N 131,20.5 r90 top
R310 "0" RESC1005X40N 127,20.5 r90 top
R311 "0" RESC1005X40N 125,8.5 r90 top
R312 "10.0K" RESC1005X40N 129.5,7.5 r180 top locked
R313 "0" RESC1005X40N 119,8.5 r90 top locked
R314 "120" RESC1005X40N 68,63.5 r0 top
R315 "120" RESC1005X40N 72,63.5 r0 top
R316 "120" RESC1005X40N 64,63.5 r0 top
R317 "100K" RESC1005X40N 72,54.9 r0 top
R318 "100K" RESC1005X40N 68,54.9 r0 top
R319 "100K" RESC1005X40N 64,54.9 r0 top
R320 "100K" RESC1005X40N 77,47 r0 top
R321 "100K" RESC1005X40N 67,47 r0 top
R322 "0" RESC1005X40N 134.5,-43.5 r0 top
R323 "0" RESC1005X40N 9,38.5 r270 top
R324 "22" RESC1005X40N 62.6,-21.5 r270 top
R325 "22" RESC1005X40N 61.6,-21.5 r270 top
R326 "0" RESC1005X40N 56.4,-41.7 r0 top
R327 "2.2K" RESC1005X40N 51.2,-47.5 r90 top
R328 "0" RESC1005X40N 50,-47.5 r90 top
R329 "2.2K" RESC1005X40N 45.8,-47.5 r270 top
R330 "0" RESC1005X40N 47,-47.5 r270 top
R331 "0" RESC1005X40N 135,-45 r270 top
R332 "0" RESC1005X40N 134.5,-46.5 r0 top
R333 "0" RESC1005X40N 132.7,-8.5 r90 top
R334 "0" RESC1005X40N 131.5,-8.5 r90 top
R335 "0" RESC1005X40N 129.5,-21.5 r0 top
R336 "0" RESC1005X40N 121,-20.5 r90 top
R337 "10.0K" RESC1005X40N 47.5,-50 r270 top
R338 "10.0K" RESC1005X40N 46,-50 r90 top
R339 "2.2M" RESC0603X28N 99,56 r270 top
R340 "0" RESC1005X40N 3.99,37.8 r180 top
R341 "100K" RESC1005X40N 45,9.5 r0 top
R342 "0" RESC1005X40N 44.5,-31.5 r270 top
R343 "0" RESC1005X40N -11.5,-38 r90 top
R344 "0" RESC1005X40N -10,-38 r90 top
R345 "0" RESC1005X40N -45,-12.8 r0 top
R346 "0" RESC1005X40N 45,1 r180 top
R347 "0" RESC1005X40N -45,-14 r0 top
R348 "100K" RESC1005X40N 45,10.5 r0 top
R349 "0" RESC1609X55N 103.3,57 r90 top
R350 "10.0K" RESC1005X40N 92.9,-35.4 r270 top
R351 "10.0K" RESC1005X40N 91.6,-35.4 r90 top
R352 "0" RESC1005X40N -45,-7 r0 top
R353 "0" RESC1005X40N -45,-8.2 r0 top
R354 "0" RESC1005X40N 44.5,-29 r90 top
R355 "0" RESC1609X55N 94.5,-56.5 r270 top
R356 "0" RESC1609X55N 92.9,-56.5 r90 top
R357 "100K" RESC1005X40N 60.5,0.5 r270 top
R358 "20K" RESC1609X55N 59,0.2 r90 top
R359 "0" RESC1005X40N 63,-5.5 r90 top
R360 "0" RESC1005X40N 61.8,-4.5 r270 top
S1 "219-4LPSTR" SOIC254P991X420-8N 133,35 r0 top locked
SW1 "KSC221JLFS" SW_KSC221J 45,43 r270 top
SW2 "KSC221JLFS" SW_KSC221J 55,43 r270 top
SW3 "KSC221JLFS" SW_KSC221J 77,43 r270 top
SW4 "KSC221JLFS" SW_KSC221J 67,43 r270 top
SWD "TC2050-IDC-NL" TC_TC2050-IDC-NL 35,62 r0 top
TP1 "TESTPOINT" TP0762 110,-10 r180 top
TP2 "TESTPOINT" TP0762 110,-14 r90 top
TP3 "TESTPOINT" TP0762 110,-6 r0 top
TP4 "TESTPOINT" TP0762 110,-2 r90 top
TP5 "TESTPOINT" TP0762 110,2 r180 top
TP6 "TESTPOINT" TP0762 125.5,38.7 r90 top
TP7 "TESTPOINT" TP0762 125.5,36.2 r90 top
U1 "STEF4SPUR" SON50P300X300X80-11T164X238N 130,47 r180 top locked
U2 "AP2202" SOT95P280X145-5N 110,57 r180 top
U3 "SIP32401A" SON50P120X160X60-5T55X91N 77.5,-47 r90 top
U4 "MP2316" QFN_MPS_MP2316 106,50 r180 top
U5 "CCWi-i.MX8M Nano" E-TEC_LPJ474-129M-32ABEW55L 0,0 r0 top locked
U6 "AB-557-03-HCHC-F-L-C" QFN50P320X250X90-15T140X210N 20,-50 r90 top locked
U7 "SN74CB3Q3245PWR" SOP65P640X120-20N 101,20 r270 top locked
U8 "AP2202" SOT95P280X145-5N -26.5,58 r180 top
U9 "FT2232D" QFP50P900X900X160-48N -22,47.5 r270 top locked
U10 "MCP2715FD" SOIC127P600X175-14N 7,48 r0 top locked
U11 "TCAN1042HGVDR" SOIC127P600X175-8N 0,53 r90 top
U12 "LTC2862IS8-2#PBF" SOIC127P600X175-8N 80,53 r90 top
U13 "SI2323DS-T1-E3" SOT95P240X110_GSD-3N -49.5,-15 r180 top
U14 "NTS0102GT" PSON50P195X100X50-8N -55,-21 r180 top
U15 "AR8031" QFN40P600X600X80-49T380N -53,-33 r0 top locked
U16 "SI2323DS-T1-E3" SOT95P240X110_GSD-3N -51,17 r0 top
U17 "NX3DV642" QFN40P340X250X50-24N 38,-47 r90 top locked
U18 "NX3DV642" QFN40P340X250X50-24N 29,-47 r90 top locked
U19 "LT8912B" QFN40P750X750X80-64N 62,-38.5 r0 top locked
U20 "CM2020-01" SOP50P640X120-38N 62.5,-50.5 r270 top locked
U21 "SN65DSI83" QFP50P1200X1200X120-65L30T320N -3,-46 r90 top locked
U22 "TPD4E001DRSR" SON95P300X300X80-7N 120.5,-48 r0 top
U23 "MIC2026" SOIC127P600X175-8N 109.5,-44.5 r270 top locked
U24 "USB2514BI-AEZG" QFN50P600X600X100-37AN 123,-37 r90 top locked
U25 "TPD4E001DRSR" SON95P300X300X80-7N 117,-14 r270 top locked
